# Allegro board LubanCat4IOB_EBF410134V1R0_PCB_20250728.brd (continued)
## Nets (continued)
GND: C1.2 C2.2 C3.2 C4.2 C5.2 C6.2 C7.2 C8.2 C11.2 C12.2 C13.2 C14.2 C15.2 C16.2 C17.2 C18.1 C19.2 C21.2 C22.2 C23.2 C24.2 C25.2 C26.2 C27.2 C28.2 C29.2 C30.2 C31.2 C32.2 C33.2 C34.2 C35.2 C36.2 C37.2 C38.2 C39.2 C40.2 C41.2 C42.2 C43.2 C44.2 C45.2 C46.2 C47.2 C48.2 C49.2 C50.2 C51.2 C52.2 C53.2 C54.2 C55.2 C58.2 C59.2 C60.2 C61.2 C62.2 C63.2 C64.2 C65.2 C66.2 C67.2 C68.2 C69.2 C70.2 C71.2 C72.2 C73.2 C74.2 C75.2 C76.2 C77.2 C78.2 C79.2 C80.2 C81.2 C82.2 C83.2 C84.2 C85.2 C86.2 C87.2 C88.2 C89.2 C90.2 C92.2 C93.2 C95.2 C96.2 C99.2 C100.2 C101.2 C102.1 C103.2 C104.2 C105.2 C106.2 C107.2 C108.2 C109.2 C110.2 C111.2 C112.2 C124.2 C125.2 C126.2 C127.2 C128.2 C129.2 C130.2 C131.2 C132.2 C133.2 C134.2 C135.2 C136.2 C137.2 C138.2 C139.2 C140.2 C141.2 C142.2 C143.2 C144.2 C147.2 C148.2 C149.2 C150.2 C151.2 C152.2 C153.2 C154.2 C155.2 C158.2 C159.2 C160.2 C161.2 C162.2 C163.2 C164.2 C165.2 C166.2 C167.2 C168.2 C169.2 C170.2 C171.2 C172.2 C173.2 C174.2 C175.2 C180.2 C181.2 C182.2 C183.2 C186.2 C187.2 C188.2 C189.2 C190.2 C192.2 C195.2 C196.2 C203.2 C204.2 C205.2 C206.2 C207.2 C209.2 C210.2 C211.2 C212.2 CN1.2 CN1.3 D1.1 D2.2(A) D6.1 D7.1 D8.1 D9.1 D10.1 D11.1 D12.1 D13.1 D14.1 D15.1 D16.1 D17.1 D18.1 D20.1 D21.1 D22.1 D24.1 D25.1 D26.1 D27.1 D29.1 D30.1 D31.1 D32.1 D33.1 D34.1 D35.2 D36.2 J1.1 J1.2 J1.3 J1.5 J2.2 J3.7 J3.8 J3.9 J3.10 J3.11 J3.12 J3.23 J3.29 J3.32 J3.38 J3.48 J3.51 J3.54 J3.64 J3.65 J3.68 J3.81 J3.82 J3.99 J3.100 J3.101(SH1) J3.102(SH2) J3.103(SH3) J3.104(SH4) J4.1 J4.2 J4.10 J4.11 J4.17 J4.18 J4.26 J4.27 J4.32 J4.37 J4.38 J4.43 J4.53 J4.54 J4.62 J4.72 J4.75 J4.82 J4.88 J4.94 J4.97 J4.99 J4.100 J5.1 J5.2 J5.11 J5.12 J5.17 J5.18 J5.27 J5.28 J5.33 J5.34 J5.44 J5.51 J5.52 J5.57 J5.58 J5.73 J5.76 J5.79 J5.82 J5.91 J5.100 J5.101(SH1) J5.102(SH2) J5.103(SH3) J5.104(SH4) J6.1 J6.2 J6.8 J6.14 J6.19 J6.20 J6.25 J6.30 J6.40 J6.43 J6.49 J6.67 J6.68 J6.78 J6.83 J6.84 J6.90 J6.96 J6.97 J6.98 J6.99 J6.100 J7.4 J8.2 J9.2 J9.5 J10.6(VSS) J10.10(GND10) J10.11(GND11) J10.12(GND12) J10.13(GND13) J15.10(CHS) J16.4(GND1) J16.7(GND2) J16.13(GND1) J16.16(NC3) J16.19(SH1) J16.20(SH2) J16.21(SH1) J16.22(SH2) J17.4(GND) J17.5(SH1) J17.6(SH2) J17.7(SH3) J17.8(SH4) J18.2(D2GND) J18.5(D1GND) J18.8(D0GND) J18.11(CKGND) J18.17(DDCGND) J19.6 J19.7 J19.8 J19.16 J19.19 J19.22 J19.25 J19.28 J19.31(SH1) J19.32(SH2) J20.6 J20.7 J20.8 J20.16 J20.19 J20.22 J20.25 J20.28 J20.31(SH1) J20.32(SH2) J21.4 J21.18 J21.21 J21.23 J21.24 J21.25(SH1) J21.26(SH2) J22.4 J22.18 J22.21 J22.23 J22.24 J22.25(SH1) J22.26(SH2) J23.4 J23.18 J23.21 J23.23 J23.24 J23.25(SH1) J23.26(SH2) J24.4 J24.18 J24.21 J24.23 J24.24 J24.25(SH1) J24.26(SH2) J25.4(GND9) J25.9(GND1) J25.15(GND2) J25.18(GND10) J25.21(GND3) J25.26(GND11) J25.27(GND4) J25.29(GND5) J25.34(GND12) J25.35(GND6) J25.37(GND7) J25.40(GND13) J25.43(GND8) J25.50(GND14) J25.53 J25.54 J30.A1(GND1) J30.A12(GND2) J30.B1(GND3) J30.B12(GND4) J31.5(GND) J31.8(SH1) J31.9(SH2) J31.10(SH3) J31.11(SH4) L5.2 L7.2 Q2.2(EMITTER) Q3.2(EMITTER) Q4.2(EMITTER) Q5.2(EMITTER) Q10.2(SOURCE) Q11.2(SOURCE) Q12.2(SOURCE) Q13.2(SOURCE) Q14.2(SOURCE) Q15.2(SOURCE) R4.2 R5.2 R7.2 R9.2 R16.2 R17.1 R20.2 R22.1 R24.2 R40.2 R41.2 R42.2 R64.2 R65.2 R72.2 R73.2 R83.2 R86.2 R91.2 R92.2 R98.2 R99.2 R100.2 R101.2 R102.2 R103.2 R121.2 R125.2 R142.2 R146.2 R157.2 R158.2 R159.2 R160.2 R166.2 R168.2 R174.2 R176.2 R202.2 R211.1 R214.2 R215.1 R217.2 R218.2 R219.2 R228.2 R229.2 R234.1 R235.2 R237.2 SS1.1(NC_1) SS2.1(NC_1) SS3.1(NC_1) SS4.1(NC_1) SS5.1(NC_1) SS6.1(NC_1) SW1.1(A1) SW1.2(A2) SW2.1(A1) SW2.2(A2) SW3.1(A1) SW3.2(A2) SW4.1(A1) SW4.2(A2) SW5.1(A1) SW5.2(A2) SW6.1(A1) SW6.2(A2) U1.2(GND) U2.2(GND) U3.1(GND) U4.2(PGND) U4.10(AGND) U5.1(\\O\E) U5.3(GND) U6.1(\\O\E) U6.3(GND) U7.1(GND1) U7.4(GND2) U8.4(VSS) U9.15(GND) U10.5(GND) U11.5(GND) U12.2(GND) U12.8(S) U13.2(GND) U13.8(S) U14.41(GND) U15.1(GND#1) U15.5(GND#5) U16.3(GND1) U16.8(GND2) U17.3(GND1) U17.8(GND2) U18.3(GND1) U18.8(GND2) U19.25(VSS) U20.2(GND) U21.2(GND) U22.3(GND1) U22.8(GND2) U23.3(GND1) U23.8(GND2) U24.2(GND) U25.2(GND) U26.2(GND) U27.2(GND) U28.2(GND) U29.2(GND) U30.1(GND) U32.2 U33.4(DGND) U33.13(HPGND) U33.18(AGND) U33.29(EPAD) U34.7(GND) U35.3(GND1) U35.8(GND2) U36.3(GND1) U36.8(GND2) U37.3(GND1) U37.8(GND2) U38.2(GND) U39.8(GND1) U39.9(GND2) U39.15(EPAD) Y2.2(GND1) Y2.4(GND2) Y3.2(GND1) Y3.4(GND2) Z1.1 Z2.1 Z3.2 Z4.2 Z5.1 Z6.1 Z7.1 Z8.1 Z9.1 Z10.1 Z11.1 Z12.1
VBUS_TYPEC: C196.1 C206.1 C207.1 J30.A4(VBUS1) J30.A9(VBUS2) J30.B4(VBUS3) J30.B9(VBUS4) U38.1(OUT) U39.2(VBUS)
VCC3V3_SYS: C10.1 C15.1 C16.1 C17.1 C132.1 C137.1 L1.2 R2.1 R6.1 U26.5(IN) U27.5(IN)
VCC5V0_SYS: C25.1 C26.1 C27.1 C28.1 C29.1 C31.1 C32.1 C107.1 C108.1 C131.1 C136.1 C189.1 C190.1 C203.1 C204.1 C205.1 J3.1 J3.2 J3.3 J3.4 J3.5 J3.6 L2.2 R11.1 R18.1 R34.1 R35.1 R36.1 R238.1 U2.5(IN) U4.5(VOUT) U20.5(IN) U21.5(IN) U24.5(IN) U25.5(IN) U28.5(IN) U29.5(IN) U34.6(VCC) U38.5(IN) U39.12(VCONN1) U39.13(VCONN2)
VCC_1V8_S0: J3.21 J3.22 R185.1 R188.1
VCC_1V8_S3: C35.1 J3.19 J3.20 R46.1 R47.1 R61.1
VCC_3V3_S3: C11.1 C36.1 C37.1 C40.1 C42.1 C211.1 D5.2 J3.13 J3.14 R1.1 R25.1 R29.1 R56.1 R230.1 R231.1 R232.1 R233.1 U5.5(VCC) U6.5(VCC) U39.3(VDD1) U39.4(VDD2)
VCC_3V3_SD: C58.1 C59.1 J10.4(VDD) R56.2
VCC_12V: C1.1 C2.1 C3.1 C12.1 C13.1 C14.1 C19.1 C21.1 C22.1 C23.1 C147.1 C148.1 C149.1 D1.2 F1.2 R8.1 R10.1 R15.1 U3.3(VIN) U4.1(VIN) U30.3(VIN)
VCCA1V8_CODEC: C164.1 C165.1 C174.1 C175.1 C187.1 R184.2 R200.1 R207.1 U33.2(DVDD) U33.3(PVDD)
VCCA3V3_CODEC: C172.1 C173.1 R186.1 R187.1 R189.2 R192.2 R205.1
VCCA_1V8_S0: C34.1 C162.1 C163.1 J3.17 J3.18 R23.1 R30.2 R32.2 R184.1
VCCA_3V3_S0: C33.1 C170.1 C171.1 J3.15 J3.16 R189.1
VDD_3V3: C5.1 C6.1 C54.1 C60.1 C61.1 C62.1 C63.1 C66.1 C67.1 C90.1 C94.1 C109.1 D19.2 D23.2 Q6.2(SOURCE) Q7.1(GATE) R43.1 R44.1 R110.1 R126.1 R127.1 R129.1 R130.1 R132.1 R133.1 R135.1 R148.1 R150.1 R152.1 R154.1 R161.1 R162.1 R163.1 R164.1 R240.2 U1.1(OUT) U9.16(VCC) U10.8(VCC) U11.8(VCC) U12.5(VIO) U13.5(VIO)
VDD_5V: C7.1 C8.1 C64.1 C65.1 C68.1 C69.1 D28.2 Q9.1(GATE) U2.1(OUT) U12.3(VCC) U13.3(VCC)
5V0_CAM0/1: C140.1 C141.1 J21.1 J21.2 J21.3 J22.1 J22.2 J22.3 U28.1(OUT)
5V0_CAM2/3: C143.1 C144.1 J23.1 J23.2 J23.3 J24.1 J24.2 J24.3 U29.1(OUT)
B_DM1: J16.2(D-) R116.1 U16.4(D2+) U16.7(NC3)
B_DM2: J16.11(D-) R112.1 U16.1(D1+) U16.10(NC1)
B_DM3: J17.2(D-) R114.1 U18.2(D1-) U18.9(NC2)
B_DP1: J16.3(D+) R117.1 U16.5(D2-) U16.6(NC4)
B_DP2: J16.12(D+) R113.1 U16.2(D1-) U16.9(NC2)
B_DP3: J17.3(D+) R115.1 U18.1(D1+) U18.10(NC1)
BAT_RTC: C50.1 D5.1 D6.2 J8.1
BD_CH3: C38.1 J4.48 R23.2 R24.1
CAM0/1_PWR_EN: J5.69 R165.1
CAM0_NRST: J4.6 J21.22
CAM0_PWDN: J4.4 J21.15
CAM1_NRST: J4.12 J22.22
CAM1_PWDN: J4.8 J22.15
CAM2/3_PWR_EN: J5.71 R167.1
CAM2_NRST: J4.16 J23.22
CAM2_PWDN: J4.14 J23.15
CAM3_NRST: J4.22 J24.22
CAM3_PWDN: J4.20 J24.15
CAN1_H: D24.2 R74.1 R78.1 U12.7(CANH)
CAN1_L: D25.2 R75.1 R78.2 U12.6(CANL)
CAN1_RX_M1: J4.30 U12.4(RXD)
CAN1_TX_M1: J4.28 U12.1(TXD)
CAN2_H: D26.2 R76.1 R79.1 U13.7(CANH)
CAN2_L: D27.2 R77.1 R79.2 U13.6(CANL)
CAN2_RX_M0: J4.36 U13.4(RXD)
CAN2_TX_M0: J4.34 U13.1(TXD)
CTP0_INT: J6.44 J19.11 R147.2
CTP0_RST: J5.62 J19.12 R151.2
CTP1_INT: J6.46 J20.11 R149.2
CTP1_RST: J6.70 J20.12 R153.2
DBG_RX: R27.2 U6.2(A)
DBG_RXD: J7.3 R27.1 Z4.1
DBG_TX: R26.2 U5.4(Y)
DBG_TXD: J7.2 R26.1 Z3.1
DEBUG_RX: J5.78 R29.2 U6.4(Y)
DEBUG_TX: J5.80 R25.2 U5.2(A)
EARPHONE_CTL: J5.72 R216.1
EXT_PWR_EN: J3.30 R3.1 R37.1
FAN: C24.1 Q1.2(SOURCE) R10.2 R11.2 R12.1
FAN_PWM: J5.63 R13.1
FUSB302_INT: J5.68 R232.2 U39.5(I\N\T\)
GMAC1_INT: J6.48 R96.1
GMAC1_MCLK_INOUT: J3.67 R97.1 R98.1
GMAC1_MDC: J3.95 R93.2 U14.13(MDC)
GMAC1_MDIO: J3.97 R94.2 U14.14(MDIO)
GMAC1_RSTN: C78.1 J6.50 R105.2 U14.12(PHYRSTB)
GMAC1_RXCLK: J3.85 R83.1 R89.1
GMAC1_RXD0: J3.87 R80.2 R84.1
GMAC1_RXD1: J3.89 R81.2 R85.1
GMAC1_RXD2: J3.91 R87.1 R91.1
GMAC1_RXD3: J3.93 R82.2 R88.1
GMAC1_RXDV_CRS: J3.83 R90.1 R92.1
GMAC1_TXCLK: J3.69 U14.20(TXC)
GMAC1_TXD0: J3.73 U14.18(TXD0)
GMAC1_TXD1: J3.75 U14.17(TXD1)
GMAC1_TXD2: J3.77 U14.16(TXD2)
GMAC1_TXD3: J3.79 U14.15(TXD3)
GMAC1_TXEN: J3.71 U14.19(TXCTL)
HDMI0_TX_ON: J6.89 R145.1
HDMI_5V: C124.1 D28.1 D34.2 J18.18(+5V) R128.1 R131.1
HDMI_EARC+: C121.2 D32.2 J18.14(UTILITY)
HDMI_EARC-: C122.2 D29.2 J18.19(HPD) R139.2
HDMI_TX0_CEC_M0: J4.60 Q9.2(SOURCE) R132.2
HDMI_TX0_D0N: C118.1 J6.37
HDMI_TX0_D0P: C117.1 J6.35
HDMI_TX0_D1N: C115.1 J6.33
HDMI_TX0_D1P: C114.1 J6.31
HDMI_TX0_D2N: C116.1 J6.29
HDMI_TX0_D2P: C113.1 J6.27
HDMI_TX0_D3N: C120.1 J6.41
HDMI_TX0_D3P: C119.1 J6.39
HDMI_TX0_HPD_M0: J6.92 Q10.3(DRAIN) R133.2
HDMI_TX0_SBDN: C122.1 J6.47
HDMI_TX0_SBDP: C121.1 J6.45
HDMI_TX0_SCL_M0: J4.56 Q7.2(SOURCE) R127.2
HDMI_TX0_SDA_M0: C123.2 J4.58 Q8.2(SOURCE) R129.2
HP_PLUG_IN_DET: C186.1 J5.46 R206.1
HUB_3V3: C110.1 C111.1 C112.1 R122.1 R123.1 R126.2 U19.1(OVCUR#) U19.20(VDD3V3)
HUB_DM1: R116.2 U19.11(DM1)
HUB_DM2: R112.2 U19.9(DM2)
HUB_DM3: R114.2 U19.7(DM3)
HUB_DM4: R182.2 U18.5(D2-) U18.6(NC4) U19.5(DM4)
HUB_DP1: R117.2 U19.12(DP1)
HUB_DP2: R113.2 U19.10(DP2)
HUB_DP3: R115.2 U19.8(DP3)
HUB_DP4: R183.2 U18.4(D2+) U18.7(NC3) U19.6(DP4)
I2C0_SCL_M2: J5.84 U8.6(SCL)
I2C0_SDA_M2: J5.86 U8.5(SDA)
I2C1_SCL_M2: J5.88 J23.6 R163.2 R230.2 U39.6(SCL)
I2C1_SDA_M2: J5.90 J23.5 R161.2 R231.2 U39.7(SDA)
I2C2_SCL_M4: J5.54 J19.9 J21.6 R148.2
I2C2_SDA_M4: J5.56 J19.10 J21.5 R152.2
I2C5_SCL_M3: J5.92 J20.9 J22.6 R150.2
I2C5_SDA_M3: J5.94 J20.10 J22.5 R154.2
I2C7_SCL_M0_CODEC: J5.77 R185.2 R197.1
I2C7_SDA_M0_CODEC: J5.75 R188.2 R198.1
I2C8_SCL_M2: J5.96 J24.6 R164.2
I2C8_SDA_M2: J5.98 J24.5 R162.2
I2C_ADDR_SET: R200.2 U33.26(CE)
I2S0_LRCK: J5.85 R194.1
I2S0_MCLK: J5.81 R190.1
I2S0_SCLK: J5.83 R191.1
I2S0_SDI0: J5.89 R195.1
I2S0_SDO0: J5.87 R193.1
LCD0_BL_PWM: J6.85 J19.13
LCD0_PWR_EN: J5.59 R156.1
LCD0_RST: J5.66 J19.15
LCD1_BL_PWM: J6.87 J20.13
LCD1_PWR_EN: J5.61 R155.1
LCD1_RST: J6.60 J20.15
MDIN0_PHY: J15.3(TD1-) U14.2(MDIN0)
MDIN1_PHY: J15.7(RD1-) U14.5(MDIN1)
MDIN2_PHY: J15.6(TD2-) U14.7(MDIN2)
MDIN3_PHY: J15.9(RD2-) U14.10(MDIN3)
MDIP0_PHY: J15.2(TD1+) U14.1(MDIP0)
MDIP1_PHY: J15.4(RD1+) U14.4(MDIP1)
MDIP2_PHY: J15.5(TD2+) U14.6(MDIP2)
MDIP3_PHY: J15.8(RD2+) U14.9(MDIP3)
MIC1_L: C176.2 C194.1 J27.2 J27.4 J29.1 R208.2 Z8.2
MIC1_R: C177.2 C194.2 J27.3 J27.5 J29.2 R218.1 Z11.2
MIC2_L: C178.2 R199.2
MIC2_R: C179.2 R201.2
MINIPCIE_3V3: C146.1 C150.1 C151.1 C152.1 C158.1 C159.1 C160.1 C161.1 J25.2(VBAT1) J25.24(VBAT5) J25.39(VBAT2) J25.41(VBAT3) J25.52(VBAT4) L6.2 R172.1 R177.1
MINIPCIE_NWDISABLE: J6.42 R180.2
MINIPCIE_PWR_EN: J5.74 R175.1
MIPI_CSI0_RX_CLK0N: J3.52 J23.10
MIPI_CSI0_RX_CLK0P: J3.50 J23.9
MIPI_CSI0_RX_CLK1N: J3.36 J24.10
MIPI_CSI0_RX_CLK1P: J3.34 J24.9
MIPI_CSI0_RX_D0N: J3.62 J23.12
MIPI_CSI0_RX_D0P: J3.60 J23.11
MIPI_CSI0_RX_D1N: J3.58 J23.8
MIPI_CSI0_RX_D1P: J3.56 J23.7
MIPI_CSI0_RX_D2N: J3.46 J24.12
MIPI_CSI0_RX_D2P: J3.44 J24.11
MIPI_CSI0_RX_D3N: J3.42 J24.8
MIPI_CSI0_RX_D3P: J3.40 J24.7
MIPI_DPHY0_RX_CLKN: J4.15 J21.10
MIPI_DPHY0_RX_CLKP: J4.13 J21.9
MIPI_DPHY0_RX_D0N: J4.25 J21.12
MIPI_DPHY0_RX_D0P: J4.23 J21.11
MIPI_DPHY0_RX_D1N: J4.21 J21.8
MIPI_DPHY0_RX_D1P: J4.19 J21.7
MIPI_DPHY0_RX_D2N: J4.9 J21.17
MIPI_DPHY0_RX_D2P: J4.7 J21.16
MIPI_DPHY0_RX_D3N: J4.5 J21.20
MIPI_DPHY0_RX_D3P: J4.3 J21.19
MIPI_DPHY0_TX_CLKN: J4.41 J19.24
MIPI_DPHY0_TX_CLKP: J4.39 J19.23
MIPI_DPHY0_TX_D0N: J4.51 J19.27
MIPI_DPHY0_TX_D0P: J4.49 J19.26
MIPI_DPHY0_TX_D1N: J4.47 J19.21
MIPI_DPHY0_TX_D1P: J4.45 J19.20
MIPI_DPHY0_TX_D2N: J4.35 J19.18
MIPI_DPHY0_TX_D2P: J4.33 J19.17
MIPI_DPHY0_TX_D3N: J4.31 J19.30
MIPI_DPHY0_TX_D3P: J4.29 J19.29
MIPI_DPHY1_RX_CLKN: J4.87 J22.10
MIPI_DPHY1_RX_CLKP: J4.85 J22.9
MIPI_DPHY1_RX_D0N: J4.95 J22.12
MIPI_DPHY1_RX_D0P: J4.93 J22.11
MIPI_DPHY1_RX_D1N: J4.91 J22.8
MIPI_DPHY1_RX_D1P: J4.89 J22.7
MIPI_DPHY1_RX_D2N: J4.83 J22.17
MIPI_DPHY1_RX_D2P: J4.81 J22.16
MIPI_DPHY1_RX_D3N: J4.79 J22.20
MIPI_DPHY1_RX_D3P: J4.77 J22.19
MIPI_DPHY1_TX_CLKN: J4.65 J20.24
MIPI_DPHY1_TX_CLKP: J4.63 J20.23
MIPI_DPHY1_TX_D0N: J4.73 J20.27
MIPI_DPHY1_TX_D0P: J4.71 J20.26
MIPI_DPHY1_TX_D1N: J4.69 J20.21
MIPI_DPHY1_TX_D1P: J4.67 J20.20
MIPI_DPHY1_TX_D2N: J4.61 J20.18
MIPI_DPHY1_TX_D2P: J4.59 J20.17
MIPI_DPHY1_TX_D3N: J4.57 J20.30
MIPI_DPHY1_TX_D3P: J4.55 J20.29
OTG_DM: D36.1 J30.A7(DN1) J30.B7(DN2) R221.1
OTG_DP: D35.1 J30.A6(DP1) J30.B6(DP2) R220.1
OUT1_L: C191.1 U33.12(LOUT1)
OUT1_R: C193.1 U33.11(ROUT1)
OUT2_L: R203.1 U33.15(LOUT2)
OUT2_R: R204.1 U33.14(ROUT2)
PCIE20_0_CLKN: J5.16 J25.11(VDD-EXT)
PCIE20_0_CLKP: J5.14 J25.13(RESERVED)
PCIE20_0_RXN: J5.6 J25.23(UART-RXD)
PCIE20_0_RXP: J5.4 J25.25(UART-RTS)
PCIE20_0_TXN: C156.1 J5.10
PCIE20_0_TXP: C157.1 J5.8
PCIE20X1_2_CLKREQN_M0: J6.54 R179.1
PCIE20X1_2_PERSTN_M0: J6.74 R181.2
PCIE20X1_2_WAKEN_M0: J6.56 R178.1
PE_TXN: C156.2 J25.31(UART-TXD)
PE_TXP: C157.2 J25.33(PERST2)
PHY1_CLKOUT125: R97.2 U14.35(CLKOUT)
PHY1_LED1: J15.14(YELA) R103.1 U14.33(LED1)
PHY1_LED2: J15.11(GRLA) R102.1 U14.34(LED2)
PWM7_IR_M0: C46.1 J5.70 R45.1
PWRON_EN: J3.24 R238.2
PWRON_KEY: C39.1 J3.28 SW1.3(B1) SW1.4(B2) Z1.2
RESET_KEY: C41.1 J3.26 SW2.3(B1) SW2.4(B2) Z2.2
RS485_1_A: D20.2 J11.1 R62.2 R67.1 U10.6(A)
RS485_1_B: D18.2 R63.1 R64.1 R66.1 U10.7(B)
RS485_2_A: D22.2 J13.1 R69.1 R70.2 U11.6(A)
RS485_2_B: D21.2 R68.1 R71.1 R72.1 U11.7(B)
RTC_32K_IN: J5.50 R48.2
RTC_INT: J5.48 R46.2 U8.3(\\I\N\T)
RXD1_232: D8.2 R51.1 U9.13(R1IN)
RXD2_232: D7.2 R49.1 U9.8(R2IN)
SARADC_BOOT: J4.52 R239.2
SARADC_IN1/REC: J4.50 R28.2
SARADC_IN4: J4.46 R31.2
SARADC_IN5: J4.44 R33.2
SBU_1: C201.1 J30.A8(SUB1) R226.1 R229.1 U37.1(D1+) U37.10(NC1)
SBU_2: C202.1 J30.B8(SUB2) R227.1 R228.1 U37.2(D1-) U37.9(NC2)
SDMMC_CLK: J6.77 R57.1
SDMMC_CMD: J6.79 R55.1
SDMMC_D0: J6.69 R58.1
SDMMC_D1: J6.71 R59.1
SDMMC_D2: J6.73 R53.1
SDMMC_D3: J6.75 R54.1
SDMMC_DET: J6.81 R60.1 R61.2
SIM_CLK0: J25.12(USIM-CLK) R171.1
SIM_DATA0: J25.10(USIM-DATA) R173.1
SIM_RST0: J25.14(USIM-RST) R170.1
SIM_VDD: J25.8(USIM-VDD) J31.1(VCC) R169.1 U32.1
SPK_CTRL: J4.24 R214.1 U34.1(SDN)
SS_TXN: C97.1 J16.8(TX-) U17.4(D2+) U17.7(NC3)
SS_TXP: C98.1 J16.9(TX+) U17.5(D2-) U17.6(NC4)
SSRX_1N: J30.B10(SSRXN1) R223.1 U35.5(D2-) U35.6(NC4)
SSRX_1P: J30.B11(SSRXP1) R222.1 U35.4(D2+) U35.7(NC3)
SSRX_2N: J30.A10(SSRXN2) R225.1 U36.5(D2-) U36.6(NC4)
SSRX_2P: J30.A11(SSRXP2) R224.1 U36.4(D2+) U36.7(NC3)
SSTX_1N: C198.1 J30.A3(SSTXN1) U35.1(D1+) U35.10(NC1)
SSTX_1P: C197.1 J30.A2(SSTXP1) U35.2(D1-) U35.9(NC2)
SSTX_2N: C200.1 J30.B3(SSTXN2) U36.1(D1+) U36.10(NC1)
SSTX_2P: C199.1 J30.B2(SSTXP2) U36.2(D1-) U36.9(NC2)
SYS_LED: J5.65 R38.1
TX_CEC_PORT: D33.2 J18.13(CEC) Q9.3(DRAIN)
TX_D0N_PORT: C118.2 J18.9(D0-) R136.1 U23.4(D2+) U23.7(NC3)
TX_D0P_PORT: C117.2 J18.7(D0+) R134.1 U23.5(D2-) U23.6(NC4)
TX_D1N_PORT: C115.2 J18.6(D1-) R138.1 U22.1(D1+) U22.10(NC1)
TX_D1P_PORT: C114.2 J18.4(D1+) R137.1 U22.2(D1-) U22.9(NC2)
TX_D2N_PORT: C116.2 J18.3(D2-) R141.1 U22.4(D2+) U22.7(NC3)
TX_D2P_PORT: C113.2 J18.1(D2+) R140.1 U22.5(D2-) U22.6(NC4)
TX_D3N_PORT: C120.2 J18.12(CK-) R144.1 U23.1(D1+) U23.10(NC1)
TX_D3P_PORT: C119.2 J18.10(CK+) R143.1 U23.2(D1-) U23.9(NC2)
TX_ON: Q12.1(GATE) Q13.1(GATE) Q14.1(GATE) Q15.1(GATE) R145.2 R146.1
TX_SCL_PORT: D31.2 J18.15(SCL) Q7.3(DRAIN) R128.2
TX_SDA_PORT: D30.2 J18.16(SDA) Q8.3(DRAIN) R131.2
TXD1_232: D10.2 R52.1 U9.14(T1OUT)
TXD2_232: D9.2 R50.1 U9.7(T2OUT)
TYPE_C_PWR_EN: J6.66 R236.1
TYPEC0_OTG_DM: J4.98 R221.2
TYPEC0_OTG_DP: J4.96 R220.2
TYPEC0_OTG_VBUSDET: J4.92 R233.2
TYPEC0_SBU1/DP0_AUXP: C201.2 J4.84
TYPEC0_SBU1_DC: J6.93 R226.2
TYPEC0_SBU2/DP0_AUXN: C202.2 J4.86
TYPEC0_SBU2_DC: J6.95 R227.2
TYPEC0_SSRX1N/DP0_TX0N: J4.80 R223.2
TYPEC0_SSRX1P/DP0_TX0P: J4.78 R222.2
TYPEC0_SSRX2N/DP0_TX2N: J4.70 R225.2
TYPEC0_SSRX2P/DP0_TX2P: J4.68 R224.2
TYPEC0_SSTX1N/DP0_TX1N: C198.2 J4.76
TYPEC0_SSTX1P/DP0_TX1P: C197.2 J4.74
TYPEC0_SSTX2N/DP0_TX3N: C200.2 J4.66
TYPEC0_SSTX2P/DP0_TX3P: C199.2 J4.64
TYPEC0_USB20_OTG_ID: J4.90 R234.2
TYPEC_CC1: C210.1 J30.A5(CC1) U37.4(D2+) U37.7(NC3) U39.10(CC1_1) U39.11(CC1_2)
TYPEC_CC2: C209.1 J30.B5(CC2) U37.5(D2-) U37.6(NC4) U39.1(CC2_1) U39.14(CC2_2)
UART0_RX_M0: J5.60 U9.9(R2OUT)
UART0_TX_M0: J5.64 U9.10(T2IN)
UART4_DIR: J6.72 R65.1 U10.2(R\E\) U10.3(DE)
UART4_RX_M2: J5.97 U10.1(RXD)
UART4_TX_M2: J5.99 U10.4(TXD)
UART7_DIR: J6.94 R73.1 U11.2(R\E\) U11.3(DE)
UART7_RX_M2: J5.93 U11.1(RXD)
UART7_TX_M2: J5.95 U11.4(TXD)
UART9_RX_M2: J6.76 U9.12(R1OUT)
UART9_TX_M2: J6.58 U9.11(T1IN)
USB20_HOST0_DM: J6.88 R120.2
USB20_HOST0_DP: J6.86 R119.2
USB20_HOST1_DM: J6.82 R109.1
USB20_HOST1_DP: J6.80 R108.1
USB20_PWR_EN: J6.64 R124.1
USB20_VBUS: C105.1 C106.1 J16.10(VBUS) J17.1(VCC) U21.1(OUT)
USB30_PWR_EN: J6.62 R118.1
USB30_SSRXN: J5.21 J16.5(RX-) U17.1(D1+) U17.10(NC1)
USB30_SSRXP: J5.19 J16.6(RX+) U17.2(D1-) U17.9(NC2)
USB30_SSTXN: C97.2 J5.25
USB30_SSTXP: C98.2 J5.23
USB30_VBUS: C99.1 C101.1 J16.1(VBUS) U20.1(OUT)
USER_LED: J5.67 R39.1
WLAN_PWR_EN: J6.52 R111.1
N02088: F1.1 J1.4
N03633: C9.1 U3.6(BOOT)
N03641: C9.2 L1.1 U3.2(SW)
N03801: C10.2 R6.2 R7.1 U3.4(FB)
N15118646: R1.2 R2.2 U1.5(IN)
N15118698: C4.1 R3.2 U1.4(EN) U2.4(EN)
N15119063: R4.1 U1.3(ISET)
N15123057: R5.1 U2.3(ISET)
N15599533: R84.2 U14.25(RXD0)
N15599537: R85.2 U14.24(RXD1)
N15599541: R87.2 U14.23(RXD2)
N15599545: R88.2 U14.22(RXD3)
N15599549: R89.2 U14.27(RXC)
N15599553: R90.2 U14.26(RXCTL)
N15600826: R95.2 R96.2 U14.31(INTB)
N15601838: C74.1 U14.37(XTAL_OUT) Y2.1
N15601846: C75.1 U14.36(XTAL_IN) Y2.3
N15602572: R104.1 U14.32(LED0)
N15603170: C76.1 J15.1(CT)
N15603215: C77.1 J15.15(SH) J15.16(SH1) R101.1
N15604636: J15.12(GRLC) R100.1
N15605512: R86.1 U14.39(RSET)
N15611443: C100.1 R118.2 U20.4(EN)
N15611553: R121.1 U20.3(ISET)
N15654067: R125.1 U21.3(ISET)
N15659726: C18.2 R8.2 R9.1 U3.5(EN)
N15752445: J18.G1(GND1) J18.G2(GND2) J18.G3(GND3) J18.G4(GND4) L5.1
N16793147: D11.2 J10.1(DAT2) R53.2
N16793149: D15.2 J10.7(DAT0) R58.2
N16793151: D14.2 J10.5(CLK) R57.2
N16793153: D13.2 J10.3(CMD) R55.2
N16793155: D12.2 J10.2(CD/DAT3) R54.2
N16793157: D16.2 J10.8(DAT1) R59.2
N16793300: D17.2 J10.9(CD) R60.2
N16811933: J25.1(MIC-P) R177.2 R178.2
N16823854: J25.7(SPK-N) R179.2
N16928945: J25.20(W-DISABLE) R180.1
N16929135: J25.22(PERST1) R181.1
N16980859: C155.1 J31.2(RST) R170.2 U32.6
N16980861: C154.1 J31.3(CLK) R171.2 U32.4
N16980863: C153.1 J31.7(I/O) R169.2 R173.2 U32.5
N17454508: C56.2 U9.1(C1+)
N17454513: C56.1 U9.3(C1-)
N17455367: C57.2 U9.4(C2+)
N17455372: C57.1 U9.5(C2-)
N17455499: C55.1 U9.6(V-)
N17455508: C53.1 U9.2(V+)
N17466585: L3.1 U14.30(REG_OUT)
N17592125: C145.1 U30.6(BOOT)
N17592129: C145.2 L6.1 U30.2(SW)
N17592172: C146.2 R172.2 R174.1 U30.4(FB)
N17592220: R175.2 R176.1 U30.5(EN)
N17633217: C103.1 U19.3(XOUT) Y3.1
N17633237: C102.2 U19.4(XIN) Y3.3
N17633305: R123.2 U19.18(PSELF)
N17633317: R122.2 U19.16(RESET#/CDP)
N17695706: C128.1 R156.2 U25.4(EN) U26.4(EN)
N17695791: R159.1 U26.3(ISET)
N17695827: R158.1 U25.3(ISET)
N17697466: J15.13(YELC) R99.1
N17697880: R166.1 U28.3(ISET)
N17697953: C139.1 R165.2 U28.4(EN)
N17702194: J12.3 R68.2
N17702199: J12.4 R69.2
N17702222: J12.2 R67.2
N17702231: J12.1 R66.2
N17728858: D19.1 R62.1
N17729021: D23.1 R70.1
N17731608: J9.4 R51.2
N17731627: J9.1 R49.2
N17750545: Q1.1(GATE) Q2.3(COLLECTOR) R12.2
N17750554: D2.1(K) J2.1 Q1.3(DRAIN)
N17750632: Q2.1(BASE) R13.2 R16.1
N17770939: R119.1 U19.15(DPU)
N17770942: R120.1 U19.14(DMU)
N17946485: C43.1 R28.1 SW3.3(B1) SW3.4(B2) Z5.2
N18056005: C94.2 Q6.1(GATE) R110.2 R111.2
N18056634: C91.1 C92.1 U15.2(RF0)
N18056637: C91.2 C93.1 CN1.1
N18057251: J25.36(USB-D-) R182.1
N18057253: J25.38(USB-D+) R183.1
N18057325: R109.2 U15.7(D-)
N18057335: R108.2 U15.6(D+)
N18111918: C125.1 R155.2 U24.4(EN) U27.4(EN)
N18111989: R160.1 U27.3(ISET)
N18112037: R157.1 U24.3(ISET)
N18115454: R168.1 U29.3(ISET)
N18115527: C142.1 R167.2 U29.4(EN)
N18211307: C30.1 R19.1 R21.1 U4.9(VCC)
N18211553: C20.2 L2.1 U4.7(SW)
N18211596: R19.2 U4.3(PG)
N18211602: R21.2 R22.2 U4.6(MODE)
N18211651: R18.2 R20.1 U4.11(FB)
N18211688: R14.1 U4.8(BST)
N18211692: C20.1 R14.2
N18213641: R15.2 R17.2 U4.12(EN)
N18241743: J30.1(SH1) J30.2(SH2) J30.3(SH3) J30.4(SH4) L7.1
N18284542: C123.1 Q8.1(GATE) R130.2
N18285221: Q10.1(GATE) Q11.3(DRAIN) R135.2
N18285616: Q11.1(GATE) R139.1 R142.1
N18287294: Q15.3(DRAIN) R134.2 R136.2
N18287307: Q14.3(DRAIN) R137.2 R138.2
N18287331: Q13.3(DRAIN) R140.2 R141.2
N18287355: Q12.3(DRAIN) R143.2 R144.2
N18312149: R198.2 U33.27(CDATA)
N18312152: R197.2 U33.28(CCLK)
N18312155: R195.2 U33.8(ASDOUT)
N18312158: R194.2 U33.7(LRCK)
N18312161: R193.2 U33.6(DSDIN)
N18312164: R191.2 U33.5(SCLK)
N18312167: R190.2 U33.1(MCLK)
N18314752: C166.1 C167.1 R186.2 U33.17(AVDD)
N18314935: C168.1 C169.1 R187.2 U33.16(HPVDD)
N18315822: C176.1 U33.24(LIN1)
N18315825: C177.1 U33.23(RIN1)
N18315828: C178.1 U33.22(LIN2)
N18315831: C179.1 U33.21(RIN2)
N18315834: C180.1 U33.20(VMID)
N18315837: C181.1 U33.19(ADCVREF)
N18315840: C182.1 U33.10(VREF)
N18319040: C184.1 P1.1(OUT) R196.2 R199.1
N18319047: C184.2 P1.2(GND) R201.1 R202.1
N18319296: C183.1 R192.1 R196.1
N18351323: J14.3 R76.2
N18351325: J14.4 R77.2
N18351329: J14.2 R75.2
N18351335: J14.1 R74.2
N18375618: D3.1(CATHODE) Q4.3(COLLECTOR)
N18375621: D3.2(ANODE) R35.2
N18375775: Q4.1(BASE) R38.2 R41.1
N18376132: D4.1(CATHODE) Q5.3(COLLECTOR)
N18376134: D4.2(ANODE) R36.2
N18376144: Q5.1(BASE) R39.2 R42.1
N18437233: R235.1 U38.3(ISET)
N18438798: R236.2 R237.1 U38.4(EN)
N18458541: C44.1 R30.1 R31.1 SW4.3(B1) SW4.4(B2) Z6.2
N18458605: C45.1 R32.1 R33.1 SW5.3(B1) SW5.4(B2) Z7.2
N18463759: LED1.1(CATHODE) Q3.3(COLLECTOR)
N18463775: LED1.2(ANODE) R34.2
N18463803: Q3.1(BASE) R37.2 R40.1
N18464833: R43.2 R45.2 U7.3(OUT)
N18464854: C47.1 C48.1 R44.2 U7.2(VCC)
N18479746: J26.1 R217.1
N18479761: J26.3 J26.5 Q17.2(SOURCE) Z10.2
N18479774: J26.2 Q16.2(SOURCE) R206.2 Z9.2
N18480030: J26.4 R205.2
N18480910: C188.1 R207.2 R208.1
N18480944: J27.1 R219.1
N18528085: J9.6 R52.2
N18528088: J9.3 R50.2
N18639472: J28.2 R212.2 U34.5(VO1)
N18639500: R209.2 R212.1 U34.4(IN-)
N18639545: C192.1 U34.2(BYPASS) U34.3(IN+)
N18639570: C185.1 R203.2 R204.2
N18639588: C185.2 R209.1
N18642135: C52.1 U8.2(OSCO) Y1.2
N18642163: C51.1 U8.1(OSCI) Y1.1
N18642204: C49.1 D5.3 U8.8(VDD)
N18642319: R47.2 R48.1 U8.7(CLKOUT)
N18645225: Q16.3(DRAIN) R210.2 R211.2
N18645232: Q17.3(DRAIN) R213.2 R215.2
N18645288: C193.2 R213.1
N18645295: C191.2 R210.1
N18645705: C195.1 Q16.1(GATE) Q17.1(GATE) R216.2
N18647092: J28.1 U34.8(VO2)
N18656178: C104.1 R124.2 U21.4(EN)
N18804334: J11.2 R63.2
N18804414: J13.2 R71.2
N18903114: C212.1 R239.1 SW6.3(B1) SW6.4(B2) Z12.2

Pads without a net: J3 25 27 31 33 35 37 39 41 43 45 47 49 53 55 57 59 61 63 66 70 72 74 76 78 80 84 86 88 90 92 94 96 98; J4 40 42; J5 3 5 7 9 13 15 20 22 24 26 29 30 31 32 35 36 37 38 39 40 41 42 43 45 47 49 53 55; J6 3 4 5 6 7 9 10 11 12 13 15 16 17 18 21 22 23 24 26 28 32 34 36 38 51 53 55 57 59 61 63 65 91; J7 1; J16 14 15 17 18; J19 14; J20 14; J21 13 14; J22 13 14; J23 13 14 16 17 19 20; J24 13 14 16 17 19 20; J25 3 5 6 16 17 19 28 30 32 42 44 45 46 47 48 49 51; J31 4 6; U4 4; U15 3 4 9 10 11 12 13 14; U19 2 13 17 19 21 22 23 24; U32 3; U33 9 25

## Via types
v1: diameter 0.508, hole 0.254, TOP to BOTTOM, 1912 vias

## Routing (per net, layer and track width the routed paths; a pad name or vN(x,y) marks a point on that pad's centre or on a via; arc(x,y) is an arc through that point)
1V05_AVDD_PHY: length 21.7
  TOP w0.381: v1(112.52,72.64) v1(110.49,72.64) 109.7,73.43 105.66,73.43 105.38,73.15 v1(104.01,73.15)
  BOTTOM w0.203: U14.8 112.63,72.53 v1(112.52,72.64) ; 108.22,69.32 U14.38 ; v1(110.49,72.64) 110.62,72.52 110.62,72.26 110.63,72.25 U14.3
  BOTTOM w0.254: C85.1 107.31,70.24 107.31,70.23 108.22,69.32
  BOTTOM w0.305: v1(110.49,72.64) C84.1 ; C83.1 112.65,72.77 v1(112.52,72.64)
  BOTTOM w0.381: C85.1 105.65,71 105.64,70.99 R107.2 C86.1 105.02,72.14 v1(104.01,73.15)
1V05_DVDD_PHY: length 1
  BOTTOM w0.203: U14.21 113.43,64.97 v1(113.51,64.9)
1V05_PHY: length 15.2
  TOP w0.381: v1(101.85,65.53) 102.45,64.93 104.27,64.93 104.65,64.55 104.65,61.85 105.03,61.47 106.55,61.47
  BOTTOM w0.381: R107.1 102.49,70.99 101.98,70.48 101.98,65.66 v1(101.85,65.53)
  vias: v1(106.3,60.07) v1(107.44,60.07)
3V3_DVDD_PHY: length 46.6
  TOP w0.254: v1(110.49,63.88) 110.49,62.69 110.23,62.44 v1(105.55,62.44) ; v1(115.44,72.64) 116.03,73.23 120.27,73.23 120.78,72.72 v1(120.78,69.72)
  TOP w0.381: 111.25,71.63 111,71.88 110.41,71.88 109.65,72.64 v1(108.84,72.64)
  ART03 w0.254: v1(110.49,63.88) 110.61,63.76 v1(117.35,63.76)
  ART03 w0.305: v1(117.35,60.32) 116.53,59.51 115.13,59.51 v1(114.3,58.67) v1(113.16,58.67)
  BOTTOM w0.203: 114.13,70.57 U14.11
  BOTTOM w0.254: R105.1 117.73,72.4 C87.1 ; R94.1 R93.1 v1(120.78,69.72) ; 114.13,70.57 114.13,70.95 114.43,71.25 v1(114.43,72.64) ; v1(117.35,63.76) v1(117.35,60.32) 117.35,60.21 R82.1 ; R81.1 v1(114.3,58.67) ; R80.1 v1(113.16,58.67)
  BOTTOM w0.305: R95.1 v1(105.55,62.44) R104.2
  BOTTOM w0.381: C89.1 v1(114.43,72.64)
  vias: v1(110.49,64.9)
3V3_IMAGE0: length 10.4
  BOTTOM w0.254: R151.1 R147.1 121.79,77.22 121.79,80.12 121.97,80.3 121.97,81.91 122.22,82.17 125.35,82.17
  vias: v1(126.87,93.09) v1(127.76,93.09)
3V3_IMAGE1: length 7
  TOP w0.254: v1(122.56,73.79) 122.56,68.59 122.56,68.58
  BOTTOM w0.254: R149.1 R153.1 v1(122.56,73.79)
3V3_WLAN:
  vias: v1(97.41,47.5) v1(98.3,47.5)
5V0_IMAGE0:
  vias: v1(127.18,87.5) v1(127.18,86.5)
GND: length 3580.5
  TOP w0.152: 39.71,36.11 v1(40.05,36.45) ; 34.92,57.44 v1(35.01,57.52) 34.92,57.6 34.92,62.42 v1(35.01,62.5) 34.92,62.58 34.92,65.58 v1(34.99,65.64) ; v1(34.67,51.81) v1(34.67,53.59) 34.92,53.85 34.92,55.03 v1(35.02,55.12) 34.92,55.21 ; 41.81,88.67 v1(41.78,88.64) ; 78.59,57.94 78.04,58.49 76.85,58.49 75.44,57.07 v1(75.44,57.02) ; v1(57.31,19.56) 57.31,21.24 59.28,23.21 ; 42.8,68.2 42.12,68.2 40.51,66.59 40.51,66.16 ; v1(36.32,65.66) v1(36.32,62.48) v1(36.32,57.53) v1(36.32,55.12) 36.32,53.08 36.59,52.81 36.59,51.96 v1(36.45,51.81) ; v1(21.46,59.05) 21.34,59.18 21.34,62.61 v1(21.08,62.86) ; 69.35,30.36 v1(69.47,30.48) ; J3.9 v1(25.31,27.05) v1(25.31,26.25) J3.10 ; v1(34.16,70.34) 34.64,69.86 37.94,69.86 ; v1(122.45,46.1) 123.6,47.25 ; 68.7,89.09 U23.8 ; U15.5 100.55,41.43 100.08,41.91 100.08,44.19 v1(99.31,44.96) 98.81,44.45 95.12,44.45 92.96,46.61 v1(92.96,47.62) ; J16.20 78.54,87.89 78.54,83.35 C147.2 ; v1(22.86,59.05) 22.99,59.18 ; J3.12 J3.11 ; 8,65.15 8.66,65.15 8.97,65.45 8.97,69.77 8.64,70.1 v1(8,70.1) ; v1(99.31,47.5) 98.68,46.86 95.12,46.86 94.49,47.5 v1(94.49,47.62) 94.49,50.54 88.9,56.13 v1(88.9,56.39) 86.74,58.55 v1(83.19,58.55) ; 36.51,30.42 v1(36.07,30.86) ; 104.78,74.42 v1(105.54,75.18) ; J3.7 J3.8 ; v1(30.48,88.26) 30.48,88.16
  TOP w0.203: J6.14 51.68,75.68 ; J5.91 v1(67.28,26.85) 65.17,26.85 64.88,27.14 J5.79 ; J6.2 J6.1 49.28,71.03 ; J6.2 49.28,75.72 ; J6.2 48.87,75.01 ; v1(29.84,76.07) 29.71,75.94 J4.32 ; v1(59.08,26.77) 59.28,26.57 J5.52 59.28,24.47 ; v1(59.08,26.77) v1(58.08,26.77) ; v1(59.08,26.77) 59.28,26.97 J5.51 59.28,28.88 ; v1(59.08,26.77) v1(60.08,26.77) ; 36.91,24.38 J3.68 36.91,26.12 v1(37.21,26.41) ; J5.103 70.26,28 ; J5.103 v1(69.35,26.85) ; J5.103 69.35,29.03 ; v1(36.45,81.28) 36.45,81.28 ; v1(35.61,26.41) 35.71,26.41 36.11,26.01 J3.64 36.11,24.52 ; J4.88 40.91,75.8 ; v1(60.08,26.77) 60.48,27.17 J5.57 60.48,28.86 ; v1(60.08,26.77) 60.48,26.37 ; J6.99 68.88,72.42 v1(69.02,72.57) ; J6.99 68.88,70.9 ; J6.99 69.4,71.61 ; J4.94 42.11,75.76 ; J6.96 J6.98 J6.100 69.36,75.01 ; 34.11,24.42 J3.54 34.11,26.45 33.71,26.85 J3.51 33.71,28.87 ; 39.71,24.37 J3.82 39.71,26.39 v1(39.73,26.41) 39.71,26.44 J3.81 39.71,28.95 ; 22.98,71.61 J4.1 23.71,70.93 ; 51.28,28.91 J5.11 51.28,27.06 v1(50.81,26.6) 51.28,26.13 J5.12 51.28,24.3 ; 49.28,24.48 J5.2 J5.1 49.28,28.91 ; 52.88,70.81 J6.19 52.88,72.31 v1(52.96,72.39) ; 57.68,24.51 J5.44 57.68,26.37 v1(58.08,26.77) ; J5.73 63.68,30.12 v1(63.35,30.45) ; J6.78 64.48,75.77 ; 29.71,24.41 J3.32 29.71,26.18 29.31,26.58 J3.29 29.31,28.91 ; 39.71,75.6 J4.82 39.71,73.61 39.31,73.2 v1(38.68,73.2) 38.51,73.03 J4.75 38.51,70.91 ; J5.100 68.88,24.46 ; 52.48,28.87 J5.17 52.48,27.19 v1(53.08,26.6) 53.03,26.6 52.48,26.05 J5.18 52.48,24.46 ; 54.48,24.51 J5.28 54.48,26.17 v1(55.08,26.77) 54.89,26.77 54.48,27.18 J5.27 54.48,28.94 ; J4.54 34.11,74.41 33.82,74.12 33.82,73.06 v1(33.86,73.02) 34.11,72.77 J4.53 34.11,70.72 ; 30.91,24.35 J3.38 30.91,26.07 31.37,26.53 v1(31.37,26.92) ; 43.31,71 J4.99 43.64,71.61 ; 69.99,25.35 J5.104 69.35,24.32 ; J6.97 68.48,70.9 ; v1(58.08,26.77) v1(57.08,26.77) v1(56.08,26.77) ; C58.2 C59.2 ; J6.8 50.48,75.7 ; J6.83 65.68,70.96 ; 30.91,70.9 J4.37 30.91,72.44 v1(31.11,72.64) 30.91,72.85 J4.38 30.91,75.64 ; v1(56.08,26.77) 55.68,27.17 J5.33 55.68,28.99 ; v1(56.08,26.77) 55.68,26.37 J5.34 55.68,24.34 ; C183.2 v1(55.88,84.58) ; J4.18 26.91,75.98 ; J6.84 65.68,75.85 ; J5.82 65.28,24.45 ; J3.48 32.91,24.39 ; J6.43 57.68,71 ; v1(63.93,24.05) 64.08,24.2 J5.76 ; 32.11,70.85 J4.43 32.11,72.5 v1(32.26,72.64) ; 43.31,24.39 J3.100 J3.99 43.31,28.97 ; J4.17 26.91,70.84 ; J4.10 25.31,73.8 v1(25.4,73.71) ; v1(28.41,26.62) 28.11,26.91 J3.23 28.11,28.7 28.37,28.96 ; 52.88,75.65 J6.20 52.88,74.45 53.29,74.04 v1(53.55,74.04) 53.55,73.41 54.08,72.88 J6.25 54.08,71 ; v1(66.95,76.2) 66.88,76.13 J6.90 ; v1(46.23,81.28) 47.12,82.17 v1(56.26,82.17) ; J6.30 54.88,75.56 ; J6.68 62.48,75.75 ; J4.72 37.71,75.77 ; J4.27 28.91,70.55 v1(28.92,70.55) ; J4.97 42.91,70.93 ; J4.2 23.15,75.01 ; J3.65 36.51,28.82 ; J4.62 35.71,75.57 ; J4.11 25.71,70.86 ; v1(61.08,26.77) 60.88,26.77 60.48,26.37 ; J4.26 28.51,75.77 ; J5.58 60.48,26.37 ; J6.49 58.88,70.91 ; J4.100 43.31,75.75 ; J6.67 62.48,70.85 ; J6.40 56.88,75.67
  TOP w0.254: J18.11 67.5,94.98 ; SW3.1 v1(5.71,26.7) ; v1(62.61,82.42) 62.65,82.46 Q13.2 ; 78.59,57.94 78.59,56.23 73.86,51.51 67.64,51.51 62.48,46.35 59.49,46.35 53.34,40.21 v1(53.34,38.35) ; U4.10 6.74,70.61 6.76,70.64 7.46,70.64 v1(8,70.1) ; J18.2 63,95.11 ; v1(64.26,88.14) U22.8 U22.3 64.26,90.61 63.88,90.99 v1(63.88,91.06) ; C76.2 122.18,82.92 v1(121.79,83.31) ; J20.19 127.84,75.74 v1(127.89,75.69) ; v1(51.94,41.45) 52.48,41.45 58.67,47.65 62,47.65 v1(64.26,49.91) 67.02,52.67 71.09,52.67 v1(75.44,57.02) ; v1(73.93,82.19) 73.36,82.19 Q12.2 73.57,82.94 R146.2 ; D36.2 32.77,93.35 v1(31.86,94.26) ; J22.21 124.68,45.75 v1(124.59,45.85) ; 127.65,74.25 J20.16 125.43,74.25 v1(125.35,74.17) ; v1(65.79,95.12) 66,94.91 J18.8 ; v1(43.05,60.3) 43.03,60.32 40.77,60.32 40.39,59.94 40.51,59.82 v1(40.51,57.53) v1(40.51,55.12) v1(40.51,52.7) 39.62,51.81 v1(38.23,51.81) v1(36.45,51.81) v1(34.67,51.81) v1(32.89,51.81) v1(31.11,51.81) 30.86,52.07 30.86,53.34 v1(31.11,53.59) v1(31.11,55.12) 31.11,55.5 32.64,57.02 32.64,62.36 32.51,62.48 v1(32.51,62.99) ; v1(81.15,49.91) 80.62,50.44 68.61,50.44 67.28,49.11 67.28,47.14 v1(67.82,46.61) v1(67.82,45.59) 66.96,44.74 59.8,44.74 55.37,40.31 v1(55.37,38.35) ; 64.24,94.97 64.5,94.71 J18.5 ; v1(62.74,54.1) 62.74,54.25 65.32,56.83 69.08,56.83 v1(73.43,61.19) 74.85,62.61 91.9,62.61 v1(92.33,62.18) ; 127.73,44.25 J22.24 125.31,44.25 ; 127.41,69.74 J20.7 125.56,69.74 ; SW3.2 v1(3.49,26.7) ; v1(65.79,82.42) 65.82,82.46 Q14.2 ; J20.28 127.87,80.25 v1(127.89,80.26) ; J18.17 70.5,94.98 ; J22.18 125.46,47.25 ; J20.25 127.88,78.74 v1(127.89,78.74) ; 125.55,69.25 J20.6 127.38,69.25 ; R174.2 v1(82.68,78.45) 85.38,78.45 87.13,80.2 93.66,80.2 v1(94.11,80.64) ; 125.55,70.25 J20.8 127.41,70.25 ; v1(127.89,77.21) 127.86,77.25 J20.22 ; v1(18.54,65.15) 18.54,65.81 19.43,66.7 19.43,70.43 19.94,70.94 23.19,70.94 ; J24.18 125.12,25.25 v1(125.09,25.27) ; J3.101 v1(22.56,28) ; v1(68.99,82.46) Q15.2 ; v1(127.64,23.75) J24.21 125.49,23.75 ; v1(47.5,62.48) 46.96,63.02 44.86,63.02 v1(44.32,62.48) 43.79,61.95 41.68,61.95 41,62.64 41,65.91 40.74,66.16 40.51,66.16 ; D35.2 v1(34.8,92.58) ; v1(68.94,88.14) 68.94,88.28 68.71,88.52 U23.8 U23.3 ; J22.23 127.73,44.75
  TOP w0.305: v1(99.31,80.64) 99.6,80.35 J25.43 ; J25.26 106.4,72.08 106.1,72.39 v1(105.79,72.39) ; J3.104 43.79,24.33 ; J3.104 v1(43.79,26.51) ; J3.104 44.62,25.35 v1(44.79,25.51) ; J5.101 48.8,26.53 v1(48.79,26.51) 48.8,26.5 J5.102 ; J5.101 48.07,28 ; J5.101 48.8,28.82 ; J22.4 127.69,54.25 ; v1(68.94,88.14) 68.94,86.44 v1(68.91,86.41) ; J3.103 44.5,28 ; J3.103 v1(43.79,26.51) ; J3.103 43.79,28.83 ; v1(43.79,26.51) v1(44.79,26.51) ; J5.102 48.8,24.49 ; J5.102 48.22,25.35 ; J25.9 116.4,77.92 116.2,77.72 v1(116.2,77.72) ; v1(118.4,72.64) J25.4
  TOP w0.381: v1(10.09,10.02) U7.1 10.09,12.38 v1(10.54,12.83) ; D11.1 v1(113.79,26.54) ; D12.1 v1(112.52,26.54) ; D14.1 v1(107.7,26.54) ; J22.26 130.3,56.31 130.3,55.5 ; v1(110.36,69.59) 109.6,70.35 J25.18 ; D29.1 74.92,90.54 v1(74.93,90.55) ; D32.1 71.89,88.87 v1(72.09,88.67) ; D16.1 v1(105.16,26.54) ; v1(14.61,10.03) 13.9,10.73 U7.4 ; C58.2 108.97,26.53 v1(108.97,26.54) ; v1(122.53,80.52) 122.45,80.44 J25.54 ; D17.1 v1(103.89,26.54) ; D13.1 v1(111.25,26.54) ; D15.1 v1(106.43,26.54) ; 16.06,23.75 16.06,24.29 SS2.1
  TOP w0.508: v1(40.05,36.45) 40.05,37.63 56.51,54.1 v1(57.66,54.1) v1(62.74,54.1) ; J25.15 114,77.89 ; SS4.1 76.45,70.2 71.35,70.2 66.04,64.89 53.03,64.89 47.38,59.24 v1(47.05,59.24) ; 100.8,69.55 J25.40 100.8,72.25 ; 96.8,69.29 J25.50 96.8,72.36 v1(96.77,72.39) ; v1(88.65,68.71) v1(82.04,68.71) v1(79.5,68.71) 71.9,68.71 v1(66.71,63.52) 53.74,63.52 v1(49.47,59.24) ; v1(91.19,73.79) 90.81,73.4 90.81,69.86 v1(89.65,68.71) ; 105.2,77.52 J25.29 105.2,80.55 v1(105.28,80.63) ; v1(102.8,77.72) J25.35 102.8,80.19 v1(103.25,80.63) ; v1(108.46,77.72) 108.4,77.78 J25.21 108.4,80.54 ; v1(89.98,77.78) 90.55,78.36 93.01,78.36 J25.53 ; 102,77.8 J25.37 102,80.4 ; J25.43 99.6,77.79 ; v1(95.63,64.26) 93.73,66.17 v1(91.91,66.17) v1(79.43,66.17) 73.23,66.17 67.59,60.53 63.54,60.53 60.93,57.92 55.14,57.92 36.44,39.22 36.44,38.42 36.44,31.23 v1(36.07,30.86) ; v1(88.65,67.41) 72.43,67.41 67.1,62.08 v1(66.72,62.08) 55.03,62.08 v1(55.02,62.1) ; J25.27 v1(106,77.72) ; J25.26 106.4,69.55 ; J25.34 103.2,72.34 v1(103.25,72.39)
  TOP w0.533: J24.26 130.34,35.45 ; J24.26 127.98,35.45 ; J24.26 129.16,36.43 ; 116.63,26.95 SS5.1 ; SS5.1 119.9,30.23 ; SS5.1 119.9,23.67 ; SS5.1 123.18,26.95 ; 127.98,57.45 J22.26 129.16,58.43 ; 116.83,21.5 J10.13 ; J10.13 117.9,22.57 ; J10.13 118.97,21.5 ; J10.13 117.9,20.44 ; J17.7 100.53,93.1 ; J17.7 97.97,93.1 ; J17.7 99.25,91.82 ; J17.7 99.25,94.38 ; 129.21,65.57 J20.32 129.21,63.62 ; 102.52,21.5 J10.10 ; J10.10 103.3,20.44 ; J10.10 103.3,22.57 ; J24.25 129.16,21.53 ; J24.25 127.98,20.55 ; J24.25 130.34,20.55 ; J24.25 129.16,19.57 ; SS6.1 95.7,30.23 ; SS6.1 95.7,23.67 ; SS6.1 92.43,26.95 ; SS6.1 98.98,26.95 ; J10.11 104.24,11.9 ; J10.11 103.3,10.52 ; J10.11 102.36,11.9 ; J10.11 103.3,13.29 ; 13.3,23.77 SS2.1 ; SS2.1 10.02,27.05 ; SS2.1 16.57,27.05 ; SS2.1 13.3,30.33 ; J17.6 104.75,94.38 ; J17.6 106.03,93.1 ; J17.6 103.47,93.1 ; J17.6 104.75,91.82 ; 18.77,99.52 J1.5 ; J1.5 18.1,100.9 ; J1.5 19.45,100.9 ; J20.31 130.39,83.39 ; J20.31 129.21,82.42 ; J20.31 128.03,83.39 ; J20.31 129.21,84.37 ; J16.7 87.64,91.88 ; J16.7 86.19,91.88 ; J16.7 86.92,91.15 ; J16.7 86.92,92.61 ; J2.2 24.74,87.53 ; J2.2 25.44,86.83 ; J2.2 24.74,86.13 ; J9.2 53.79,13.05 ; J9.2 52.71,11.97 ; J9.2 51.64,13.05 ; 40.21,13.05 J9.5 ; J9.5 42.36,13.05 ; J9.5 41.28,11.97 ; J16.19 82.12,95.38 ; J16.19 80.35,93.6 ; J16.19 78.57,95.38 ; J8.2 18.57,85.21 ; J8.2 17.94,84.58 ; J8.2 17.94,85.83 ; 17,93.65 J1.3 ; J1.3 17.92,95.18 ; J1.3 18.85,93.65 ; J1.3 17.92,92.12 ; J22.25 129.16,43.53 ; J22.25 130.34,42.55 ; J22.25 129.16,41.57 ; 82.69,90.18 J16.13 ; J16.13 84.14,90.18 ; J16.13 83.42,90.91 ; 27.77,11.51 J7.4 ; J7.4 28.75,12.49 ; J7.4 29.73,11.51 ; J16.4 84.14,93.38 ; J16.4 83.42,94.11 ; J16.4 82.69,93.38 ; 86.19,88.68 J16.16 ; J17.5 104.75,87.38 ; J17.5 104.75,84.82 ; J17.5 106.03,86.1 ; J17.5 103.47,86.1 ; 93.49,93.6 J16.22 ; J16.22 91.71,95.38 ; J16.22 95.27,95.38 ; J1.2 13.55,93.65 ; J1.2 12.63,92.12 ; J1.2 11.7,93.65 ; J1.2 12.63,95.18 ; 80.35,87.92 J16.20 ; J16.20 80.35,91.48 ; J16.20 82.12,89.7 ; 117.86,11.9 J10.12 ; J10.12 118.8,13.29 ; J10.12 118.8,10.52 ; J10.12 119.74,11.9 ; 97.97,86.1 J17.8 ; J17.8 99.25,87.38 ; J17.8 100.53,86.1 ; J17.8 99.25,84.82 ; J16.21 95.27,89.7 ; J16.21 91.71,89.7 ; J16.21 93.49,91.48 ; J16.21 93.49,87.92 ; 8.3,100.9 J1.1 ; J1.1 9.65,100.9 ; J1.1 8.98,99.52 ; J17.4 102.68,86.6 ; J17.4 102,87.27 ; J17.4 102,85.92 ; J17.4 101.32,86.6 ; SS3.1 79.3,30.33 ; SS3.1 76.02,27.05 ; SS3.1 79.3,23.77 ; SS3.1 82.57,27.05 ; SS4.1 82.57,73.05 ; SS4.1 79.3,76.33 ; SS4.1 76.02,73.05 ; 13.3,69.77 SS1.1
  GND02 w0.381: J16.16 87.64,88.68 ; J16.16 86.92,89.41 ; J16.16 86.19,88.68 ; 91.71,89.7 J16.21 ; J16.21 93.49,91.48 ; J16.21 93.49,87.92 ; J16.21 95.27,89.7 ; 8.98,99.52 J1.1 ; J1.1 8.98,102.28 ; J1.1 9.65,100.9 ; J1.1 8.3,100.9 ; J16.19 80.35,97.16 ; J16.19 82.12,95.38 ; J16.19 78.57,95.38 ; J16.19 80.35,93.6 ; SS1.1 16.07,73.05 ; SS1.1 10.52,73.05 ; SS1.1 13.3,70.27 ; SS1.1 13.3,75.83 ; 95.7,24.17 SS6.1 ; SS6.1 92.93,26.95 ; SS6.1 95.7,29.73 ; SS6.1 98.48,26.95 ; J9.5 42.36,13.05 ; J9.5 41.28,14.13 ; J9.5 40.21,13.05 ; J9.5 41.28,11.97 ; J1.3 17.92,95.18 ; J1.3 18.85,93.65 ; J1.3 17.92,92.12 ; J1.3 17,93.65 ; 10.52,27.05 SS2.1 ; SS2.1 13.3,29.83 ; SS2.1 13.3,24.27 ; SS2.1 16.07,27.05 ; J16.7 86.92,92.61 ; J16.7 86.19,91.88 ; J16.7 87.64,91.88 ; J16.7 86.92,91.15 ; J16.22 93.49,97.16 ; J16.22 95.27,95.38 ; J16.22 93.49,93.6 ; J16.22 91.71,95.38 ; 18.1,100.9 J1.5 ; J1.5 18.77,99.52 ; J1.5 18.77,102.28 ; J1.5 19.45,100.9 ; 97.97,86.1 J17.8 ; J17.8 100.53,86.1 ; J17.8 99.25,87.38 ; J17.8 99.25,84.82 ; 83.42,92.65 J16.4 ; J16.4 82.69,93.38 ; J16.4 84.14,93.38 ; J16.4 83.42,94.11 ; 78.57,89.7 J16.20 ; J16.20 82.12,89.7 ; J16.20 80.35,91.48 ; J16.20 80.35,87.92 ; J17.5 106.03,86.1 ; J17.5 103.47,86.1 ; J17.5 104.75,87.38 ; J17.5 104.75,84.82 ; SS5.1 119.9,29.73 ; SS5.1 117.13,26.95 ; SS5.1 119.9,24.17 ; SS5.1 122.68,26.95 ; 11.7,93.65 J1.2 ; J1.2 12.63,95.18 ; J1.2 12.63,92.12 ; J1.2 13.55,93.65 ; J9.2 53.79,13.05 ; J9.2 52.71,11.97 ; J9.2 52.71,14.13 ; J9.2 51.64,13.05 ; J16.13 84.14,90.18 ; J16.13 83.42,89.45 ; J16.13 82.69,90.18 ; J16.13 83.42,90.91 ; J2.2 24.74,87.53 ; J2.2 24.74,86.13 ; J2.2 25.44,86.83 ; J2.2 24.04,86.83 ; SS3.1 79.3,29.83 ; SS3.1 76.52,27.05 ; SS3.1 79.3,24.27 ; SS3.1 82.07,27.05 ; J17.7 100.53,93.1 ; J17.7 99.25,91.82 ; J17.7 97.97,93.1 ; J17.7 99.25,94.38 ; 104.75,91.82 J17.6 ; J17.6 106.03,93.1 ; J17.6 103.47,93.1 ; J17.6 104.75,94.38 ; 101.32,86.6 J17.4 ; J17.4 102,87.27 ; J17.4 102,85.92 ; J17.4 102.68,86.6 ; J8.2 18.57,85.21 ; J8.2 17.94,85.83 ; J8.2 17.94,84.58 ; SS4.1 82.07,73.05 ; SS4.1 76.52,73.05 ; SS4.1 79.3,75.83 ; SS4.1 79.3,70.27 ; J7.4 29.73,11.51 ; J7.4 28.75,10.53 ; J7.4 28.75,12.49 ; J7.4 27.77,11.51
  GND02 w0.762: J15.10 107.94,87.75
  ART03 w0.152: v1(45.85,68.32) 45.46,67.94 34.68,67.94 34.42,68.2 34.78,68.56 34.78,69.72 v1(34.16,70.34) ; v1(53.62,23.44) 52.86,24.21 51.26,24.21 v1(50.29,23.24) 49.38,24.15 47.19,24.15 v1(46.46,23.42) ; v1(129.67,67.69) 129.67,66.52 128.85,65.71 128.35,65.71 v1(127.89,66.17) ; v1(25.53,61.85) 25.11,61.85 23.01,63.94 21.25,63.94 20.99,64.21 20.99,65.68 20.62,66.04 ; v1(57.31,19.56) 57.92,20.17 59.73,20.17 v1(60.47,19.43) ; v1(124.08,60.32) 124.08,59.87 ; v1(80.9,20.19) 83.74,20.19 85.01,21.46 89.41,21.46 v1(90.17,20.7) ; v1(91.95,20.7) 92.89,19.76 98.76,19.76 99.85,20.85 v1(99.85,21.08) ; v1(105.54,64.26) 109.76,64.26 109.98,64.48 118.14,64.48 v1(118.87,63.75) ; v1(127.89,73.66) 128.27,74.04 v1(129.67,74.04) ; 71.19,86.41 v1(71.27,86.49) ; 123.06,59.87 v1(123.06,60.32) ; v1(38.68,24.13) 38.71,24.15 v1(40.94,24.15) ; v1(0.76,77.09) v1(0.76,76.07) v1(0.76,75.05) v1(0.76,74.04) v1(0.76,73.02) v1(0.76,70.1) v1(0.76,66.29) v1(0.76,62.48) v1(0.76,60.67) v1(0.76,59.67) v1(0.76,58.67) v1(0.76,57.67) v1(0.76,56.67) v1(0.76,55.67) v1(0.76,54.67) v1(0.76,51.05) v1(0.76,47.24) v1(0.76,43.43) v1(0.76,39.62) ; v1(45.59,84.71) 43.56,82.68 v1(43.43,82.68)
  ART03 w0.254: 102.88,30.44 103.24,30.08 114.5,30.08 117.06,32.64 v1(117.98,32.64) ; v1(61.85,86.36) 68.82,86.36 68.87,86.41 v1(68.91,86.41) 71.19,86.41
  ART03 w0.305: v1(118.87,63.75) 119.89,64.77 v1(123.06,64.77) v1(124.08,64.77) 125.93,64.77 127.33,66.17 v1(127.89,66.17) ; v1(31.11,55.12) v1(26.29,55.12) v1(23.37,55.12) 21.21,55.12 v1(20.45,55.88) v1(18.92,55.88) 17.91,56.89 17.91,64.29 ; v1(31.11,55.12) v1(33.4,55.12) 33.41,55.12 v1(35.02,55.12) 35.02,55.12 v1(36.32,55.12) v1(37.72,55.12) v1(40.51,55.12) v1(42.42,55.12) v1(44.96,55.12) 46.61,55.12 v1(47.24,55.75) 47.8,56.31 v1(47.8,56.59) 47.83,56.56 v1(49.43,56.56) 49.91,56.08 v1(49.91,55.75) v1(51.44,55.75) 73.87,55.75 v1(73.94,55.68) 75.84,53.78 98.17,53.78 v1(98.2,53.82) 98.23,53.78 v1(103.82,53.78) 104.27,53.33 116.08,53.33 v1(119.25,50.16) v1(120.52,50.16) 121.3,49.39 122.67,49.39 v1(122.81,49.53) 123.17,49.89 123.17,50.78 v1(123.32,50.93) 123.35,50.9 v1(125.22,50.9) v1(125.22,52.7) ; v1(31.11,55.12) v1(31.11,53.59) 30.9,53.37 30.9,52.03 v1(31.11,51.81) 33.15,49.78 v1(35.94,49.78) 43.69,49.78 v1(44.33,50.42) v1(45.59,50.42) v1(61.47,50.42) 63.75,50.42 v1(64.26,49.91) 64.45,49.72 v1(68.5,49.72) 69.99,49.72 v1(72.39,47.32) 72.95,46.76 77.23,46.76 77.71,47.24 v1(79.12,47.24) v1(87,47.24) v1(91.57,47.24) 91.95,47.62 v1(92.96,47.62) v1(94.49,47.62) 95.17,46.94 98.76,46.94 99.15,47.33 ; v1(125.22,52.7) 125.86,53.34 v1(127.64,53.34) v1(128.65,53.34) 129.26,52.73 v1(129.26,51.94) 129.26,48.49 v1(128.91,48.13) 128.91,47.63 127.85,46.58 125.32,46.58 v1(124.59,45.85) 124.59,45.59 v1(123.95,44.96) 123.95,43.98 123.59,43.62 121.36,43.62 v1(120.78,44.19) 119.38,44.19 115.97,47.61 v1(112.27,47.61) ; v1(125.22,52.7) 125.22,57.32 124.92,57.63 122.57,57.63 121.78,58.42 118.76,58.42 v1(117.87,59.31) 117.23,58.67 v1(115.44,58.67) 114.84,58.07 112.61,58.07 v1(112.01,58.67) v1(110.87,58.67) v1(109.86,58.67) v1(107.44,58.67) v1(106.3,58.67) 105.28,59.69 v1(105.28,60.07) v1(104.39,60.96) 103.87,60.43 95.12,60.43 94.66,60.9 ; v1(98.3,64.27) 98.8,64.27 99.47,63.6 102.08,63.6 v1(102.74,64.26) v1(105.54,64.26) ; 94.66,60.9 87.02,60.9 86.73,61.19 v1(73.43,61.19) 73.29,61.05 60.55,61.05 v1(59.5,62.1) 59.5,62.1 v1(55.02,62.1) 54.96,62.16 v1(49.57,62.16) 49.4,62 44.75,62 v1(43.05,60.3) 27.46,60.3 v1(27.43,60.32) 25.78,60.32 25.32,60.78 25.32,61.64 v1(25.53,61.85) ; 94.66,60.9 95.56,61.81 95.56,64.19 v1(95.63,64.26) ; v1(127.89,73.66) 126.82,73.66 124.65,71.49 123.23,71.49 122.75,71.02 95.41,71.02 v1(95.28,70.89) 93.75,70.89 v1(93.73,70.86) 88.99,70.86 88.65,70.52 v1(88.65,68.71) v1(88.65,67.41) 79.44,67.41 v1(79.44,67.41) 76,67.41 v1(75.97,67.39) ; v1(49.4,68.96) v1(48.13,68.96) 46.48,68.96 v1(45.85,68.32) ; 27.62,71.61 22.05,66.04 20.62,66.04 ; v1(132.24,68.15) v1(132.24,45.29)
  ART03 w0.381: v1(128.27,24.38) v1(128.27,26.41) v1(128.27,28.57) 128.27,28.95 v1(127.64,29.59)
  ART03 w0.508: SS1.1 12.12,74.23 12.12,82.67 12.88,83.44 14.32,83.44 14.86,82.9 v1(14.86,82.29) ; v1(129.67,67.69) v1(129.67,69.21) v1(129.67,70.74) v1(129.67,72.26) v1(129.67,74.04) v1(129.67,75.56) v1(129.67,77.4) v1(129.67,78.74) v1(129.67,80.26) v1(129.67,82.07) 126.46,82.07 122.96,78.57 118.84,78.57 117.99,77.72 v1(116.2,77.72) v1(114.17,77.72) 114.17,77.72 v1(112.01,77.72) v1(110.62,77.72) v1(108.46,77.72) 108.45,77.72 v1(106,77.72) v1(102.8,77.72) 90.04,77.72 v1(89.98,77.78) 89.31,78.45 v1(82.68,78.45) 80.04,78.45 79.67,78.08 66.3,78.08 65.71,78.68 ; v1(60.47,19.43) 61.23,20.19 v1(72.9,20.19) v1(75.56,20.19) v1(80.9,20.19) ; 34.42,68.2 26.98,68.2 26.44,67.66 v1(26.44,65) 26.14,64.69 26.14,63.86 26.27,63.73 26.27,62.59 v1(25.53,61.85) ; v1(95.63,64.26) 95.64,64.27 v1(98.3,64.27) ; v1(34.16,70.34) 32.26,72.24 v1(32.26,72.64) ; 33.89,76.96 v1(41.66,76.96) 41.99,76.63 46.79,76.63 v1(47.37,77.21) 47.61,76.97 v1(52.88,76.97) 57.42,76.97 59.97,79.53 ; 9.53,35.41 7.49,33.37 7.49,32.05 ; v1(112.27,47.61) v1(111.27,47.61) v1(110.27,47.61) v1(109.27,47.61) v1(108.27,47.61) v1(107.27,47.61) v1(106.27,47.61) v1(105.27,47.61) v1(104.27,47.61) 99.43,47.61 v1(99.31,47.5) 99.15,47.33 ; v1(132.24,94.82) v1(132.24,91.01) v1(132.24,87.2) v1(132.24,83.39) v1(132.24,79.58) v1(132.24,75.77) v1(132.24,71.96) v1(132.24,68.15) ; 70.72,24.64 v1(70.35,25) 69.86,25 69.35,25.51 v1(69.35,26.85) v1(67.28,26.85) 66.7,27.43 61.74,27.43 v1(61.08,26.77) v1(60.08,26.77) v1(59.08,26.77) v1(58.08,26.77) v1(57.08,26.77) v1(56.08,26.77) v1(55.08,26.77) 54.91,26.6 v1(53.08,26.6) 53.08,26.62 52.52,27.18 51.37,27.18 50.81,26.62 v1(50.81,26.6) 50.73,26.51 v1(48.79,26.51) v1(47.79,26.51) v1(46.79,26.51) v1(44.79,26.51) v1(43.79,26.51) 43.69,26.41 v1(39.73,26.41) v1(37.21,26.41) v1(35.61,26.41) 34.99,26.41 34.34,25.76 33.06,25.76 32.26,24.96 v1(32.26,23.62) 32.5,23.38 32.5,22.27 31.66,21.43 30.97,21.43 30.47,21.93 30.47,23.23 v1(30.86,23.62) 28.92,23.62 28.41,24.13 v1(28.41,26.62) 28.41,29.58 v1(29.57,30.74) 35.95,30.74 v1(36.07,30.86) 43.07,30.86 v1(43.45,30.48) v1(48.15,30.48) v1(51.94,30.48) 63.32,30.48 v1(63.35,30.45) 65.53,32.64 v1(78.36,32.64) v1(86.36,32.64) v1(94.23,32.64) v1(98.42,32.64) v1(99.82,32.64) 100.68,32.64 102.88,30.44 ; 70.72,24.64 70.35,24.27 v1(70.35,24) v1(69.35,24) 69.3,24.05 v1(63.93,24.05) 63.32,23.44 v1(55.62,23.44) v1(54.62,23.44) v1(53.62,23.44) ; 70.72,24.64 v1(74.68,24.64) 75.56,25.53 v1(75.56,29.08) 77.27,29.08 SS3.1 81.33,29.08 v1(87.25,29.08) v1(91.06,29.08) 93.57,29.08 SS6.1 96.11,26.54 v1(102.74,26.54) v1(103.89,26.54) v1(105.16,26.54) v1(106.43,26.54) v1(107.7,26.54) v1(108.97,26.54) v1(111.25,26.54) v1(112.52,26.54) v1(113.79,26.54) 119.49,26.54 SS5.1 120.28,27.33 124.23,27.33 v1(124.71,27.81) 125.86,27.81 v1(127.64,29.59) 127.95,29.59 128,29.54 128.54,29.54 128.59,29.59 v1(128.91,29.59) 129.03,29.72 v1(129.03,31.37) 129.02,31.37 128.75,31.63 126.35,31.63 v1(125.09,32.89) v1(124.08,32.89) 121.03,32.89 v1(120.78,32.64) v1(117.98,32.64) ; v1(128.27,24.38) 128.27,24.38 v1(127.64,23.75) 127.26,23.75 v1(125.22,21.72) 124.84,21.33 106.08,21.33 v1(105.38,20.64) 104.94,21.08 v1(99.85,21.08) ; v1(40.94,24.15) 45.72,24.15 v1(46.46,23.42) ; 17.91,64.29 17.91,64.51 v1(18.54,65.15) 19.43,66.04 20.62,66.04 ; v1(90.17,20.7) v1(91.95,20.7) ; v1(57.31,19.56) v1(56.31,19.56) 55.67,18.92 42.04,18.92 v1(40.51,20.45) 40.18,20.12 35.89,20.12 v1(35.56,20.45) 35.07,19.96 34.58,19.96 34.06,20.47 34.06,22.1 v1(34.29,22.33) 34.29,23.62 34.8,24.13 v1(38.68,24.13) ; v1(0.76,35.81) v1(0.76,39.62)
  ART03 w0.533: 18.77,99.52 J1.5 ; J1.5 19.45,100.9 ; J1.5 18.1,100.9 ; 93.49,93.6 J16.22 91.71,95.38 ; 93.49,87.92 J16.21 ; J16.21 91.71,89.7 ; J16.21 93.49,91.48 ; J16.21 95.27,89.7 ; 83.42,89.45 J16.13 ; J16.13 83.42,90.91 ; J16.13 82.69,90.18 ; J16.13 84.14,90.18 ; J16.16 86.92,89.41 ; J16.16 87.64,88.68 ; J16.16 86.19,88.68 ; J8.2 17.94,85.83 ; SS2.1 16.07,27.05 ; SS2.1 13.3,24.27 ; SS2.1 13.3,29.83 ; J17.8 100.53,86.1 ; J17.8 99.25,84.82 ; J17.8 97.97,86.1 ; J17.8 99.25,87.38 ; 83.42,92.65 J16.4 ; J16.4 84.14,93.38 ; J16.4 82.69,93.38 ; J16.4 83.42,94.11 ; J9.5 42.36,13.05 ; J9.5 40.21,13.05 ; J9.5 41.28,11.97 ; J9.5 41.28,14.13 ; 78.57,89.7 J16.20 ; J16.20 80.35,91.48 ; J16.20 82.12,89.7 ; J16.20 80.35,87.92 ; 12.63,92.12 J1.2 ; J1.2 11.7,93.65 ; J1.2 13.55,93.65 ; J1.2 12.63,95.18 ; 28.75,10.53 J7.4 ; J7.4 29.73,11.51 ; J7.4 28.75,12.49 ; J7.4 27.77,11.51 ; 51.64,13.05 J9.2 ; J9.2 52.71,11.97 ; J9.2 53.79,13.05 ; J9.2 52.71,14.13 ; 13.3,70.27 SS1.1 ; SS1.1 13.3,75.83 ; SS1.1 16.07,73.05 ; 86.19,91.88 J16.7 ; J16.7 87.64,91.88 ; J16.7 86.92,92.61 ; J16.7 86.92,91.15 ; 80.35,93.6 J16.19 ; J16.19 78.57,95.38 ; J16.19 82.12,95.38 ; 104.75,91.82 J17.6 ; J17.6 106.03,93.1 ; J17.6 103.47,93.1 ; 8.3,100.9 J1.1 ; J1.1 8.98,99.52 ; J1.1 9.65,100.9 ; 101.32,86.6 J17.4 ; J17.4 102.68,86.6 ; J17.4 102,87.27 ; J17.4 102,85.92 ; 103.47,86.1 J17.5 ; J17.5 106.03,86.1 ; J17.5 104.75,87.38 ; J17.5 104.75,84.82 ; J1.3 17.92,95.18 ; J1.3 18.85,93.65 ; J1.3 17,93.65 ; J17.7 100.53,93.1 ; J17.7 97.97,93.1 ; J17.7 99.25,91.82
  PWR04 w0.533: 8.3,100.9 J1.1 ; J1.1 9.65,100.9 ; J1.1 8.98,99.52 ; 52.71,11.97 J9.2 ; 28.75,10.53 J7.4 ; J7.4 29.73,11.51 ; J7.4 27.77,11.51 ; 18.77,99.52 J1.5 ; J1.5 19.45,100.9 ; J1.5 18.1,100.9 ; J17.6 106.03,93.1 ; J1.2 12.63,95.18 ; 41.28,11.97 J9.5 ; J1.3 17.92,95.18
  GND05 w0.381: J1.2 12.63,95.18 ; J1.2 11.7,93.65 ; J1.2 12.63,92.12 ; J1.2 13.55,93.65 ; J1.3 17.92,95.18 ; J1.3 17.92,92.12 ; J1.3 17,93.65 ; J1.3 18.85,93.65 ; 13.3,24.27 SS2.1 ; SS2.1 13.3,29.83 ; SS2.1 16.07,27.05 ; SS2.1 10.52,27.05 ; 82.69,90.18 J16.13 ; J16.13 83.42,89.45 ; J16.13 83.42,90.91 ; J16.13 84.14,90.18 ; 13.3,70.27 SS1.1 ; SS1.1 16.07,73.05 ; SS1.1 13.3,75.83 ; SS1.1 10.52,73.05 ; J7.4 29.73,11.51 ; J7.4 28.75,10.53 ; J7.4 28.75,12.49 ; J7.4 27.77,11.51 ; 86.19,88.68 J16.16 ; J16.16 87.64,88.68 ; J16.16 86.92,89.41 ; J9.5 41.28,14.13 ; J9.5 42.36,13.05 ; J9.5 41.28,11.97 ; J9.5 40.21,13.05 ; J16.19 82.12,95.38 ; J16.19 80.35,93.6 ; J16.19 78.57,95.38 ; J16.19 80.35,97.16 ; 80.35,87.92 J16.20 ; J16.20 80.35,91.48 ; J16.20 82.12,89.7 ; J16.20 78.57,89.7 ; J17.4 102,87.27 ; J17.4 102,85.92 ; J17.4 102.68,86.6 ; J17.4 101.32,86.6 ; J17.8 99.25,87.38 ; J17.8 100.53,86.1 ; J17.8 97.97,86.1 ; J17.8 99.25,84.82 ; J17.7 99.25,94.38 ; J17.7 97.97,93.1 ; J17.7 100.53,93.1 ; J17.7 99.25,91.82 ; J16.7 87.64,91.88 ; J16.7 86.92,92.61 ; J16.7 86.19,91.88 ; J16.7 86.92,91.15 ; J16.4 83.42,94.11 ; J16.4 83.42,92.65 ; J16.4 82.69,93.38 ; J16.4 84.14,93.38 ; 18.1,100.9 J1.5 ; J1.5 19.45,100.9 ; J1.5 18.77,99.52 ; J1.5 18.77,102.28 ; J16.21 95.27,89.7 ; J16.21 93.49,87.92 ; J16.21 93.49,91.48 ; J16.21 91.71,89.7 ; J17.5 106.03,86.1 ; J17.5 104.75,87.38 ; J17.5 103.47,86.1 ; J17.5 104.75,84.82 ; 95.7,24.17 SS6.1 ; SS6.1 92.93,26.95 ; SS6.1 98.48,26.95 ; SS6.1 95.7,29.73 ; J8.2 18.57,85.21 ; J8.2 17.94,84.58 ; J8.2 17.94,85.83 ; J16.22 95.27,95.38 ; J16.22 93.49,93.6 ; J16.22 91.71,95.38 ; J16.22 93.49,97.16 ; 76.52,73.05 SS4.1 ; SS4.1 82.07,73.05 ; SS4.1 79.3,70.27 ; SS4.1 79.3,75.83 ; 76.52,27.05 SS3.1 ; SS3.1 79.3,24.27 ; SS3.1 82.07,27.05 ; SS3.1 79.3,29.83 ; J1.1 8.98,102.28 ; J1.1 8.98,99.52 ; J1.1 9.65,100.9 ; J1.1 8.3,100.9 ; 119.9,24.17 SS5.1 ; SS5.1 119.9,29.73 ; SS5.1 122.68,26.95 ; SS5.1 117.13,26.95 ; 52.71,11.97 J9.2 ; J9.2 51.64,13.05 ; J9.2 52.71,14.13 ; J9.2 53.79,13.05 ; J2.2 25.44,86.83 ; J2.2 24.74,86.13 ; J2.2 24.74,87.53 ; J2.2 24.04,86.83 ; 104.75,91.82 J17.6 ; J17.6 106.03,93.1 ; J17.6 104.75,94.38 ; J17.6 103.47,93.1
  GND05 w0.762: J15.10 107.82,87.75
  BOTTOM w0.152: 93.19,64.68 95.21,64.68 v1(95.63,64.26) ; C186.2 47.24,93.99 47.24,86.23 v1(47.12,86.1) ; v1(99.31,80.64) 99.31,79.97 101.56,77.72 v1(102.8,77.72) ; v1(106.3,58.67) 103.78,61.19 91.37,61.19 90.7,60.52 90.7,59.92 91.19,59.43 v1(91.19,59.05) 91.52,59.05 92,59.54 96.93,59.54 97.64,60.25 102.92,60.25 105.83,57.34 110.07,57.34 110.87,58.14 v1(110.87,58.67) ; v1(73.03,85.09) 71.27,83.34 69.86,83.34 v1(68.99,82.46) 67.73,81.2 65.39,81.2 64.62,80.43 ; 73,73.4 71.37,73.4 70.87,72.9 70.87,70.74 70.31,70.18 65.46,70.18 65.15,69.87 65.15,53.47 66.5,52.12 94.69,52.12 v1(96.65,50.16) v1(99.31,47.5) v1(99.31,44.96) ; v1(62.99,42.29) 62.84,42.14 61.04,42.14 58.72,44.45 58.72,51.36 60.33,52.96 60.33,55.72 61.11,56.5 61.11,71.06 60.71,71.47 60.71,72.87 60.81,72.97 60.81,74.37 60.71,74.47 ; C24.2 v1(11.81,62.36) ; 114,83.25 113.08,82.33 113.08,76.16 ; C55.2 v1(38.62,41.9) ; v1(75.44,57.02) 75.95,56.51 77.59,56.51 78.11,57.02 ; v1(80.14,58.55) 81.28,58.55 81.66,58.16 81.66,57.71 v1(81.76,57.61) ; 12.42,76.34 10.48,74.4 10.48,71.96 11,71.44 11,71.21 11.18,71.03 11.18,69.97 ; v1(81.41,80.9) 82.04,80.26 82.8,80.26 83.1,80.56 83.1,83.84 83.01,83.93 83.01,84.76 v1(81.15,86.61) 80.65,87.12 78.61,87.12 ; v1(52.96,72.39) 52.83,72.39 52.45,72.77 C187.2 ; 71.25,85.58 70.17,84.5 69.15,84.5 67.07,82.42 v1(65.79,82.42) ; 8.43,71.34 9.07,70.7 9.07,69.31 ; v1(118.87,63.75) v1(118.87,60.32) 118.87,58.8 113.79,53.72 103.89,53.72 v1(103.82,53.78) 102.87,54.74 102.87,55.24 102.23,55.88 v1(102.23,56.39) 102.87,56.39 104.65,54.61 112.78,54.61 117.48,59.31 v1(117.87,59.31) 117.86,59.32 117.86,63.93 117.55,64.24 116.61,64.24 115.95,64.9 114.3,64.9 113.95,65.25 v1(113.95,66.01) ; v1(98.68,68.32) 98.48,68.53 98.48,75.68 ; 36.17,84.94 36.17,85.34 ; R4.2 25.52,39.77 C4.2 ; 8.89,75.61 8.59,75.3 8.59,71.54 ; 99.72,76.49 96.88,79.34 96.88,84.72 ; 30.66,83.45 33.07,85.86 33.07,87.52 32.84,87.74 31.45,87.74 30.99,87.29 ; 110.48,81.97 110.48,82.45 ; v1(43.81,94.36) 43.81,94.23 46.58,91.46 46.58,86.8 ; C31.2 v1(17.14,27.68)
  BOTTOM w0.178: U33.4 U33.29
  BOTTOM w0.203: J24.21 v1(127.64,23.75) ; v1(113.79,31.49) 113.92,31.37 U32.2 ; Z8.1 51.43,80.21 v1(51.15,80.48) 51.15,81.25 52.15,82.24 53.26,82.24 53.47,82.45 53.47,85.72 v1(53.09,86.1) ; v1(47.37,74.67) 48.39,75.69 49.92,75.69 C188.2 ; v1(47.37,79.75) Z11.1 ; v1(45.85,68.32) U33.18 47.98,68.32 48.13,68.48 v1(48.13,68.96) ; v1(39.07,81.3) 39.75,80.62 39.75,77.34 ; v1(48.13,67.69) 47.87,67.43 U33.13 47.87,65.59 v1(47.59,65.31) 44.76,62.48 v1(44.32,62.48)
  BOTTOM w0.254: v1(95.63,64.26) 95.76,64.39 U18.3 U18.8 98.17,64.39 98.3,64.26 v1(98.3,64.27) ; 42.91,50.29 41.66,50.29 41.55,50.18 41.55,50.18 41.2,49.84 41.2,49.84 41.15,49.78 41.15,47.55 40.84,47.24 35.81,47.24 v1(35.05,46.48) 34.26,45.69 34.26,42.65 32,40.38 32,33.78 v1(33.15,32.64) ; 42.91,50.29 44.2,50.29 v1(44.33,50.42) U9.15 44.33,46.99 ; 42.91,50.29 42.42,49.8 42.42,46.73 v1(42.16,46.48) 41.91,46.23 36.57,46.23 35.15,44.81 35.15,42.14 32.87,39.85 32.87,35.3 v1(33.12,35.05) 36.83,35.05 37.08,34.8 37.08,26.54 v1(37.21,26.41) 37.21,15.75 36.17,14.71 36.17,12.22 36.58,11.81 40.62,11.81 41.28,12.47 J9.5 ; C186.2 47.79,94.11 v1(47.8,94.11) ; v1(2.67,52.07) 3.17,52.07 3.43,52.32 R7.2 ; v1(88.95,86.38) 88.9,86.33 U16.3 U16.8 ; R40.2 v1(7.37,19.05) ; v1(99.82,32.64) v1(99.82,35.18) v1(99.82,38.23) 99.82,44.45 v1(99.31,44.96) ; 78.61,87.12 78.16,86.66 78.16,84.82 76.37,83.03 74.55,83.03 73.93,82.4 v1(73.93,82.19) 73.91,82.18 73.54,82.18 69.57,78.21 ; J19.19 v1(127.89,72.24) ; 44.33,46.99 42.29,44.96 v1(42.11,44.96) v1(38.61,44.96) 37.34,44.96 37.34,40.13 39.12,38.35 D10.1 ; 44.33,46.99 45.35,45.97 46.35,45.97 C53.2 ; v1(61.47,50.42) 63.25,52.2 63.25,72.15 62.99,72.4 ; v1(127.89,73.66) 127.8,73.74 J19.16 125.77,73.74 v1(125.35,74.17) ; 44.96,22.48 44.96,18.19 47.73,15.42 47.73,12.34 48.39,11.68 51.35,11.68 J9.2 52.71,15.86 46.25,22.33 ; v1(103.89,26.54) v1(102.74,26.54) ; v1(68.2,95.12) 68.58,95.12 69.15,95.69 Q10.2 ; U17.8 U17.3 v1(84.45,86.36) 84.45,86.87 v1(83.95,87.37) ; v1(99.31,80.64) 99.31,82.29 99.82,82.8 101.46,82.8 v1(102.23,82.03) ; R42.2 v1(13.72,19.05) ; J21.18 127.23,52.75 127.48,53 127.48,53.19 v1(127.64,53.34) ; v1(81.41,80.9) 81.29,81.02 R176.2 ; J19.25 v1(127.89,69.24) ; Z10.1 v1(44.7,86.74) ; v1(79.12,47.24) 79.12,50.04 79.53,50.44 80.62,50.44 v1(81.15,49.91) 81.66,50.42 R73.2 ; v1(106.51,66.24) 106.55,66.28 C75.2 105.64,66.81 Y2.2 105.27,67.09 104.4,66.22 103.14,66.22 102.8,66.56 v1(102.8,68.32) v1(102.8,69.47) Y2.4 103.77,69.52 104.66,70.4 105.99,70.4 C74.2 106.93,69.47 v1(107.31,69.47) ; J19.28 v1(127.89,67.74) ; Z9.1 v1(45.09,95.88) ; v1(116.46,72.64) 116.71,72.39 C78.2 ; v1(36.45,97.92) U37.3 U37.8 v1(36.45,95.49) ; R41.2 v1(10.67,19.05) ; R218.2 v1(47.37,77.21) ; 129.29,61.33 v1(129.29,61.34) ; R9.2 C18.1 v1(2.67,56) ; J19.22 v1(127.89,70.74)
  BOTTOM w0.305: U6.3 29.71,16.37 v1(29.72,16.38) ; v1(93.85,72.39) 93.84,72.38 C112.2 ; v1(24.13,16.38) 24.12,16.37 U5.3 ; R102.2 v1(102.74,64.26) ; v1(91.95,20.7) 91.95,20.57 ; Z3.2 v1(23.74,14.3) ; v1(23.24,69.47) U39.9 21.44,69.47 ; Z4.2 v1(26.3,14.3) ; U5.1 24.11,17.67 v1(24.13,17.65) ; R92.2 v1(112.01,58.67) ; U39.8 21.33,68.97 ; R86.2 v1(107.82,75.18) ; v1(28.32,19.81) 28.31,19.8 C42.2 ; C153.2 v1(115.44,34.8) ; R91.2 v1(115.44,58.67) ; U6.1 29.7,17.67 v1(29.72,17.66) ; v1(102.72,62.89) 102.79,62.89 103.02,63.12 R103.2 ; R98.2 v1(102.74,65.53) ; C154.2 v1(116.71,34.8) ; C83.2 v1(112.65,75.18) ; R83.2 v1(110.87,58.67) ; C89.2 v1(114.43,75.18) ; C155.2 v1(114.17,34.8) ; C84.2 v1(110.49,75.18) ; v1(88.95,87.48) v1(88.95,86.38) ; C88.2 v1(108.84,75.18)
  BOTTOM w0.381: v1(118.4,72.64) 118.75,72.29 C158.2 ; C169.2 C168.2 45.08,65.67 v1(45.09,65.66) ; C102.1 93.73,65.91 v1(95.63,65.91) 96.51,66.79 Y3.2 97.54,68.2 v1(97.54,68.32) v1(97.54,69.49) 97.54,70.36 97.16,70.74 96.14,70.74 95.01,69.61 Y3.4 94.64,69.84 C103.2 v1(93.73,70.86) ; v1(103.25,72.39) 103.38,72.26 103.77,72.26 C86.2 ; R215.1 v1(36.45,81.28) ; v1(105.54,75.18) 106.31,74.41 C160.2 ; C47.2 v1(11.56,12.82) ; v1(105.79,72.39) 106.18,72 C85.2 ; C46.2 v1(14.61,10.03) ; C48.2 v1(10.54,12.83) ; R211.1 v1(43.43,81.28) ; D34.1 72.09,88.97 v1(72.09,88.67) ; v1(55.02,62.1) 55.02,62.25 55.24,62.47 C174.2 C175.2 ; R234.1 43.31,71.63 43.32,71.62 C180.2 C181.2 43.32,68.71 C167.2 C166.2 44.84,68.7 45.21,68.32 v1(45.85,68.32)
  BOTTOM w0.508: U12.2 v1(72.39,47.32) ; 91.18,73.78 v1(91.19,73.79) ; U12.8 71.12,42.74 v1(70.67,42.29) ; R219.2 v1(44.7,99.82) ; 50.49,28.45 50.49,53.62 50.29,53.82 50.29,53.85 49.91,54.23 v1(49.91,55.75) ; U13.8 v1(62.99,42.29) ; v1(75.44,57.02) 74.65,57.02 73,58.67 73,74.78 78.08,79.86 80.37,79.86 v1(81.41,80.9) ; v1(53.34,38.35) v1(53.34,45.01) 53.34,57.32 52.22,58.44 50.27,58.44 v1(49.47,59.24) ; v1(80.14,58.55) 79.45,59.23 79.45,60.43 78.93,60.43 75.89,63.47 75.89,73.95 79.05,77.12 83.6,77.12 86.36,79.88 v1(86.36,80.9) ; v1(127.64,56.89) 128.19,57.45 J22.26 129.16,58.8 v1(129.29,58.93) ; v1(84.58,80.9) 84.58,80.35 v1(82.68,78.45) 78.49,78.45 74.41,74.37 74.41,62.69 77.6,59.51 77.6,57.66 78.11,57.15 78.11,57.02 ; C60.2 v1(87,47.24) ; 51.94,29.17 v1(51.94,30.48) v1(51.94,35.43) v1(51.94,38.35) v1(51.94,41.45) v1(51.94,45.01) 51.94,55.24 v1(51.44,55.75) ; 47.96,28.52 48.9,29.46 v1(48.9,35.43) v1(48.9,38.35) 48.9,52.96 47.24,54.61 v1(47.24,55.75) ; R72.2 v1(80.78,42.29) ; U13.2 v1(64.26,49.91) ; U11.5 v1(84.33,42.29) ; R217.2 v1(47.24,101.09) ; U10.5 v1(92.2,42.29) ; C61.2 v1(79.12,47.24) ; J15.10 108.72,87.75 ; R64.2 v1(88.65,42.29)
  BOTTOM w0.533: 51.64,13.05 J9.2 ; J9.2 52.71,11.97 ; J9.2 53.79,13.05 ; 28.75,10.53 J7.4 ; J7.4 28.75,12.49 ; J7.4 29.73,11.51 ; J7.4 27.77,11.51 ; J8.2 17.94,85.83 ; J8.2 18.57,85.21 ; J8.2 17.94,84.58 ; J16.19 82.12,95.38 ; J16.19 80.35,93.6 ; J16.19 80.35,97.16 ; 97.97,93.1 J17.7 ; J17.7 99.25,94.38 ; J17.7 100.53,93.1 ; J17.4 102.68,86.6 ; J17.4 102,87.27 ; J17.4 102,85.92 ; J17.4 101.32,86.6 ; 86.19,88.68 J16.16 ; J16.16 87.64,88.68 ; J16.16 86.92,89.41 ; J16.20 82.12,89.7 ; 103.47,93.1 J17.6 ; J17.6 104.75,94.38 ; J17.6 106.03,93.1 ; J17.6 104.75,91.82 ; J2.2 24.74,87.53 ; J2.2 24.74,86.13 ; J2.2 25.44,86.83 ; 18.77,99.52 J1.5 ; J1.5 18.1,100.9 ; J1.5 19.45,100.9 ; 129.21,63.62 J20.32 129.21,65.57 ; 127.98,20.55 J24.25 ; J24.25 130.34,20.55 ; J24.25 129.16,19.57 ; J24.25 129.16,21.53 ; 86.19,91.88 J16.7 ; J16.7 86.92,92.61 ; J16.7 87.64,91.88 ; 10.52,27.05 SS2.1 ; SS2.1 13.3,24.27 ; SS2.1 13.3,29.83 ; 104.75,84.82 J17.5 ; J17.5 103.47,86.1 ; J17.5 106.03,86.1 ; J17.5 104.75,87.38 ; J9.5 42.36,13.05 ; J9.5 41.28,14.13 ; J9.5 40.21,13.05 ; 117.5,19.54 J31.8 ; J31.8 117.5,21.99 ; J31.8 118.18,20.76 ; J1.3 17.92,95.18 ; J1.3 17,93.65 ; J1.3 18.85,93.65 ; J1.3 17.92,92.12 ; J1.2 13.55,93.65 ; J1.2 12.63,95.18 ; J1.2 11.7,93.65 ; J1.2 12.63,92.12 ; 92.93,26.95 SS6.1 ; SS6.1 98.48,26.95 ; SS6.1 95.7,24.17 ; SS6.1 95.7,29.73 ; J31.9 104.5,21.99 ; J31.9 103.82,20.76 ; J31.9 105.18,20.76 ; J31.9 104.5,19.54 ; 129.16,41.57 J22.25 ; J22.25 130.34,42.55 ; J22.25 129.16,43.53 ; J31.10 117.5,9.99 ; J31.10 118.18,8.76 ; J31.10 116.82,8.76 ; 8.98,99.52 J1.1 ; J1.1 8.3,100.9 ; J1.1 9.65,100.9 ; J16.22 93.49,97.16 ; J16.22 91.71,95.38 ; J16.22 93.49,93.6 ; J16.22 95.27,95.38 ; J20.31 130.39,83.39 ; J20.31 129.21,82.42 ; J20.31 129.21,84.37 ; SS3.1 79.3,29.83 ; SS3.1 76.52,27.05 ; SS3.1 82.07,27.05 ; SS3.1 79.3,24.27 ; 91.71,89.7 J16.21 95.27,89.7 ; 103.82,8.76 J31.11 ; J31.11 105.18,8.76 ; J31.11 104.5,9.99 ; 13.3,70.27 SS1.1 13.3,75.83 ; SS4.1 82.07,73.05 ; SS4.1 79.3,75.83 ; SS4.1 76.52,73.05 ; SS4.1 79.3,70.27 ; 127.98,35.45 J24.26 ; J24.26 130.34,35.45 ; J24.26 129.16,36.43 ; 82.69,93.38 J16.4 ; J16.4 83.42,94.11 ; J16.4 84.14,93.38 ; 82.69,90.18 J16.13 ; 99.25,84.82 J17.8 ; J17.8 99.25,87.38 ; J17.8 100.53,86.1 ; J17.8 97.97,86.1 ; 119.9,29.73 SS5.1 119.9,24.17
  vias: v1(0.84,100.58) v1(0.76,96.77) v1(0.76,93.63) v1(0.76,92.63) v1(0.76,91.63) v1(0.76,90.63) v1(0.76,89.63) v1(0.76,88.63) v1(0.76,87.63) v1(0.76,86.49) v1(0.76,85.34) v1(0.76,84.07) v1(0.76,81.53) v1(0.76,32) v1(0.76,28.19) v1(0.76,24.38) v1(0.76,20.57) v1(0.76,16.76) v1(0.76,12.95) v1(1.78,83.44) v1(1.78,81.53) v1(2.03,93.63) v1(2.03,92.63) v1(2.03,91.63) v1(2.03,90.63) v1(2.03,89.63) v1(2.03,88.63) v1(2.03,87.63) v1(2.67,59) v1(2.67,58) v1(2.67,57) v1(2.79,76.97) v1(2.79,76.07) v1(2.79,75.05) v1(2.79,74.04) v1(2.79,73.02) v1(3.03,93.63) v1(3.03,92.63) v1(3.03,91.63) v1(3.3,83.44) v1(3.3,80.9) v1(3.43,22.24) v1(3.43,17.92) v1(3.56,31) v1(3.71,35.55) v1(4.03,93.63) v1(4.03,92.63) v1(4.03,91.63) v1(4.48,7.76) v1(4.57,16.76) v1(5.03,93.63) v1(5.03,92.63) v1(5.03,91.63) v1(5.54,22.42) v1(5.59,31.13) v1(5.65,17.92) v1(5.92,68.73) v1(6.03,93.63) v1(6.03,92.63) v1(6.03,91.63) v1(5.97,51.05) v1(5.97,50.04) v1(6.33,56.64) v1(7.03,93.63) v1(7.03,92.63) v1(7.03,91.63) v1(7.03,90.63) v1(7.03,89.63) v1(7.03,88.63) v1(7.03,87.63) v1(6.99,51.05) v1(6.99,50.04) v1(6.99,43.18) v1(7.33,56.64) v1(7.37,82.87) v1(7.44,59.69) v1(7.44,58.69) v1(8.03,87.63) v1(8.03,86.63) v1(7.98,51.04) v1(7.98,50.04) v1(8,43.18) v1(8,42.18) v1(8,41.18) v1(8.08,102.24) v1(8.08,98.43) v1(8.13,24) v1(8.33,56.64) v1(8.29,11.57) v1(8.29,7.76) v1(8.44,64.69) v1(8.44,63.69) v1(8.44,62.69) v1(8.44,61.69) v1(8.44,60.69) v1(8.44,59.69) v1(8.44,58.69) v1(8.64,39.75) v1(10.39,77.93) v1(10.67,14.35) v1(11.7,97.43) v1(11.7,96.43) v1(11.81,63.36) v1(11.81,52.56) v1(11.81,51.56) v1(11.81,50.56) v1(11.81,49.56) v1(11.81,48.56) v1(11.81,47.56) v1(11.81,46.56) v1(11.81,45.56) v1(11.81,44.56) v1(11.81,43.56) v1(11.89,102.24) v1(12.06,79.25) v1(12.06,78.25) v1(12.1,7.76) v1(12.7,97.43) v1(12.7,96.43) v1(13.46,36.96) v1(13.46,36.15) v1(13.46,35.15) v1(13.46,34.15) v1(13.46,33.15) v1(13.7,97.43) v1(13.7,96.43) v1(13.72,14.35) v1(13.92,86.77) v1(14.46,37.15) v1(14.46,36.15) v1(14.46,35.15) v1(14.46,34.15) v1(14.46,33.15) v1(14.7,97.43) v1(14.7,96.43) v1(14.7,95.43) v1(14.7,94.43) v1(14.7,93.43) v1(14.92,87.77) v1(14.92,86.77) v1(14.92,85.77) v1(15.08,79.48) v1(15.08,78.48) v1(15.37,14.35) v1(15.46,37.15) v1(15.46,36.15) v1(15.46,35.15) v1(15.46,34.15) v1(15.46,33.15) v1(15.62,47.12) v1(15.62,44.07) v1(15.7,102.24) v1(15.7,98.43) v1(15.7,97.43) v1(15.7,96.43) v1(15.7,95.43) v1(15.7,94.43) v1(15.7,93.43) v1(15.92,87.77) v1(15.92,86.77) v1(15.91,7.76) v1(16.08,81.48) v1(16.08,80.48) v1(16.08,79.48) v1(16.27,12.7) v1(16.51,45.08) v1(16.51,19.81) v1(16.7,98.43) v1(16.7,97.43) v1(16.7,96.43) v1(16.76,50.04) v1(16.76,48.89) v1(17.14,30.68) v1(17.14,29.68) v1(17.14,28.68) v1(17.35,35.15) v1(17.35,34.15) v1(17.35,33.15) v1(17.43,25.49) v1(17.43,24.49) v1(17.43,23.49) v1(17.7,98.43) v1(17.7,97.43) v1(17.7,96.43) v1(18.14,30.68) v1(18.14,29.68) v1(18.21,75.08) v1(18.31,77.01) v1(18.43,25.49) v1(18.43,24.49) v1(18.43,23.49) v1(18.54,79.22) v1(18.57,59.87) v1(18.7,98.43) v1(18.7,97.43) v1(18.7,96.43) v1(18.75,63.45) v1(18.9,54.17) v1(18.9,53.17) v1(18.9,52.17) v1(18.92,50.04) v1(18.92,47.12) v1(18.92,45.08) v1(19,9.57) v1(19.14,34.38) v1(19.14,33.38) v1(19.14,32.38) v1(19.43,25.49) v1(19.43,24.49) v1(19.43,23.49) v1(19.51,102.24) v1(19.56,14.35) v1(19.7,98.43) v1(19.7,97.43) v1(19.7,96.43) v1(19.7,95.43) v1(19.68,91.95) v1(19.68,62.86) v1(19.72,7.76) v1(19.82,69.21) v1(19.89,57.86) v1(20.14,34.38) v1(20.14,33.38) v1(20.14,32.38) v1(20.19,19.81) v1(20.32,37.72) v1(20.43,25.49) v1(20.43,24.49) v1(20.45,23.49) v1(20.57,50.04) v1(20.57,47.12) v1(20.65,54.17) v1(20.65,53.17) v1(20.65,52.17) v1(20.82,69.21) v1(20.82,68.21) v1(20.95,93.85) v1(21,77.99) v1(21,76.99) v1(21,75.99) v1(21.08,100.2) v1(21.26,70.91) v1(21.46,47.12) v1(21.65,54.17) v1(21.65,53.17) v1(21.65,52.17) v1(22,77.99) v1(22.23,91.95) v1(22.2,50.06) v1(22.61,88.77) v1(22.68,95.55) v1(22.73,57.53) v1(22.79,98.55) v1(22.81,9.57) v1(22.99,24.3) v1(22.99,23.5) v1(23.11,91.95) v1(23.5,89.79) v1(23.53,7.76) v1(24,93.85) v1(24,78.99) v1(24,50.04) v1(24,43.05) v1(23.99,24.3) v1(23.99,23.5) v1(24.13,51.97) v1(24.1,47.88) v1(24.1,37.84) v1(24.64,84.71) v1(24.62,82.29) v1(24.64,57.53) v1(24.66,95.55) v1(24.77,30.74) v1(24.77,29.74) v1(24.99,24.3) v1(24.99,23.5) v1(25.15,89.79) v1(25.27,101.09) v1(25.37,98.55) v1(25.4,95.12) v1(25.79,24.3) v1(26.29,101.09) v1(26.29,57.6) v1(26.29,56.37) v1(26.29,51.81) v1(26.43,50.04) v1(26.62,9.57) v1(26.67,76.83) v1(26.92,70.56) v1(27.23,37.62) v1(27.3,47.88) v1(27.3,46.48) v1(27.3,43.05) v1(27.3,41.78) v1(27.34,7.76) v1(27.43,50.04) v1(27.56,86.36) v1(27.56,84.83) v1(27.58,51.84) v1(27.57,33.74) v1(27.57,32.74) v1(27.81,65.02) v1(27.88,92.07) v1(28.19,89.28) v1(28.32,78.23) v1(28.32,61.85) v1(28.43,50.04) v1(29.02,86.99) v1(29.08,51.81) v1(29.08,46.48) v1(29.1,41.78) v1(29.34,65.02) v1(29.43,50.04) v1(29.46,99.54) v1(29.57,31.74) v1(29.97,82.24) v1(29.97,46.48) v1(29.97,41.78) v1(29.97,19.81) v1(30.29,92.45) v1(30.41,56.37) v1(30.43,9.57) v1(30.51,90.37) v1(30.51,57.53) v1(30.48,36.45) v1(30.58,94.97) v1(30.73,101.09) v1(30.99,65.02) v1(30.99,49.15) v1(31.11,62.99) v1(31.11,14.73) v1(31.18,95.88) v1(31.15,11.57) v1(31.15,7.76) v1(31.41,56.37) v1(31.51,57.53) v1(31.62,80.64) v1(32.26,73.8) v1(32.41,56.37) v1(32.51,57.53) v1(32.89,53.59) v1(33.73,65.68) v1(33.76,57.49) v1(33.75,56.38) v1(33.91,101.22) v1(33.91,85.22) v1(33.91,36.45) v1(34.1,86.74) v1(34.46,97.94) v1(34.75,102.24) v1(34.8,78.89) v1(34.92,36.45) v1(35,56.38) v1(34.96,11.57) v1(34.96,7.76) v1(35.51,73) v1(35.53,9.57) v1(35.59,86.65) v1(35.81,94.23) v1(35.94,48.26) v1(36.25,56.42) v1(36.7,92.05) v1(37.03,22.71) v1(37.08,86.74) v1(37.06,73.02) v1(37.55,65.38) v1(37.72,92.05) v1(38.42,70.34) v1(38.48,97.15) v1(38.56,102.24) v1(38.81,62.49) v1(38.84,57.57) v1(38.77,11.57) v1(38.77,7.76) v1(39.12,85.85) v1(39.34,9.57) v1(39.75,84.58) v1(40.39,82.29) v1(40.39,81.28) v1(41.05,36.45) v1(41.66,84.58) v1(42.05,36.45) v1(42.19,23.47) v1(42.29,52.96) v1(42.37,102.24) v1(42.42,57.53) v1(42.58,11.57) v1(42.58,7.76) v1(43.05,36.45) v1(43.15,9.57) v1(43.31,62.48) v1(43.43,88.39) v1(43.69,92.58) v1(43.97,74.65) v1(43.98,71.95) v1(44.05,36.45) v1(44.27,23.37) v1(44.7,89.53) v1(44.83,57.53) v1(44.79,27.51) v1(44.96,32.75) v1(44.96,31.75) v1(45.09,81.28) v1(45.85,74.67) v1(45.85,36.45) v1(46.18,102.24) v1(46.18,98.43) v1(46.39,11.57) v1(46.39,7.76) v1(46.53,50.45) v1(46.74,83.95) v1(46.79,27.51) v1(46.79,25.51) v1(46.86,36.45) v1(46.96,9.57) v1(47.12,41.4) v1(47.5,45.03) v1(47.79,27.51) v1(47.79,25.51) v1(48.13,86.1) v1(48.13,31.75) v1(48.26,41.4) v1(49.4,67.69) v1(49.66,91.18) v1(49.66,86.1) v1(49.65,80.48) v1(49.99,102.24) v1(49.99,98.43) v1(50.2,11.57) v1(50.2,7.76) v1(50.42,32.03) v1(50.51,48.08) v1(50.55,41.4) v1(50.55,38.35) v1(50.55,35.43) v1(50.57,90.27) v1(50.67,97.41) v1(50.67,95.88) v1(50.77,9.57) v1(51.53,70.6) v1(52.65,80.48) v1(52.96,95.88) v1(52.96,94.36) v1(53.09,88.01) v1(53.34,35.43) v1(53.34,31.42) v1(53.49,84.61) v1(53.52,82.19) v1(53.8,102.24) v1(54.01,11.57) v1(54.01,7.76) v1(54.48,93.47) v1(54.58,9.57) v1(54.74,88.01) v1(55.75,95.88) v1(55.75,93.47) v1(56.13,36.45) v1(56.1,31.49) v1(56.1,30.49) v1(57.15,90.68) v1(57.1,32.49) v1(57.1,31.49) v1(57.1,30.49) v1(57.61,102.24) v1(57.61,98.43) v1(57.82,11.57) v1(57.82,7.76) v1(58.1,32.49) v1(58.1,31.49) v1(58.1,30.49) v1(58.42,88.77) v1(58.36,74.11) v1(58.41,70.49) v1(58.39,9.57) v1(58.79,60.32) v1(58.96,69.3) v1(59.05,68.16) v1(59.1,33.49) v1(59.1,32.49) v1(59.1,31.49) v1(59.1,30.49) v1(59.18,90.68) v1(59.29,63.52) v1(59.41,70.49) v1(59.66,60.01) v1(59.84,57.93) v1(60.1,30.49) v1(60.53,88.14) v1(60.45,33.53) v1(60.71,82.42) v1(61.42,102.24) v1(61.42,98.43) v1(61.59,91.06) v1(61.63,11.57) v1(61.63,7.76) v1(61.98,88.14) v1(62.1,46.38) v1(62.23,36.45) v1(62.23,35.43) v1(62.2,9.57) v1(62.48,95.12) v1(62.65,81.41) v1(63.5,36.45) v1(63.5,35.43) v1(64.26,97.15) v1(64.64,46.35) v1(64.74,79.69) v1(65.23,102.24) v1(65.23,98.43) v1(65.28,77.58) v1(65.25,76.24) v1(65.41,99.57) v1(65.43,15.54) v1(65.44,11.57) v1(65.44,7.76) v1(65.47,65.23) v1(66.01,9.57) v1(66.55,88.14) v1(66.93,96.26) v1(67.06,80.39) v1(67.06,14.35) v1(67.25,36.47) v1(67.25,35.46) v1(67.63,69.6) v1(67.82,43.56) v1(68.25,36.47) v1(68.25,35.47) v1(68.58,80.39) v1(69.04,102.24) v1(69.25,11.57) v1(69.25,7.76) v1(69.68,62.64) v1(69.82,9.57) v1(69.94,76.2) v1(69.99,57.8) v1(70.63,36.45) v1(70.63,35.43) v1(70.94,76.2) v1(71.02,30.48) v1(71.25,88.14) v1(71.17,66.06) v1(71.37,95.12) v1(71.94,76.2) v1(72.14,87.23) v1(72.85,102.24) v1(72.9,98.42) v1(73.03,71.75) v1(73.06,11.57) v1(73.06,7.76) v1(74.17,14.35) v1(74.26,80.03) v1(74.42,36.45) v1(74.42,35.43) v1(74.88,87.71) v1(75.69,36.45) v1(75.69,35.43) v1(75.82,44.19) v1(76.05,68.71) v1(75.96,66.16) v1(76.45,23.37) v1(76.66,102.24) v1(76.71,98.42) v1(76.87,11.57) v1(76.87,7.76) v1(77.6,41.4) v1(77.6,36.45) v1(77.67,9.57) v1(78.99,19.05) v1(79.5,44.19) v1(79.76,36.45) v1(79.76,35.18) v1(79.88,81.41) v1(80.01,100.58) v1(80.01,23.37) v1(80.47,102.24) v1(80.47,9.57) v1(80.68,11.57) v1(80.68,7.76) v1(81.03,36.45) v1(81.03,35.18) v1(82.19,58.55) v1(82.17,19.05) v1(83.57,75.06) v1(83.68,73.16) v1(83.82,36.45) v1(83.82,35.18) v1(84.28,102.24) v1(84.33,44.96) v1(84.28,9.57) v1(84.49,11.57) v1(84.49,7.76) v1(85.09,36.45) v1(85.09,35.18) v1(85.67,56.72) v1(85.85,99.06) v1(85.85,94.99) v1(85.98,87.5) v1(85.98,86.36) v1(86.36,50.42) v1(86.87,100.07) v1(86.87,99.06) v1(86.87,73.28) v1(87,44.58) v1(87.25,25.27) v1(87.25,14.1) v1(87.63,36.45) v1(87.63,35.18) v1(87.76,50.42) v1(87.88,99.06) v1(88.09,102.24) v1(88.09,9.57) v1(88.3,11.57) v1(88.3,7.76) v1(88.9,36.45) v1(88.9,35.18) v1(89.15,96.52) v1(89.15,94.23) v1(89.65,67.41) v1(90.17,19.3) v1(90.81,100.07) v1(90.81,99.06) v1(91.06,25.27) v1(91.57,50.42) v1(91.69,86.36) v1(91.69,36.45) v1(91.69,35.18) v1(91.9,102.24) v1(91.9,98.43) v1(91.9,9.57) v1(92.11,11.57) v1(92.11,7.76) v1(92.71,86.36) v1(92.96,36.45) v1(92.96,35.18) v1(93.73,86.36) v1(94.11,74.93) v1(94.61,38.23) v1(94.61,35.18) v1(94.74,86.36) v1(94.74,43.81) v1(94.74,41.53) v1(94.87,14.1) v1(95.5,90.68) v1(95.71,102.24) v1(95.71,9.57) v1(95.76,86.36) v1(95.76,85.34) v1(95.92,11.57) v1(95.92,7.76) v1(97.41,90.68) v1(97.54,74.93) v1(97.66,42.16) v1(98.19,56.39) v1(98.42,38.23) v1(98.42,35.18) v1(99.19,99.06) v1(99.19,56.39) v1(99.19,55.12) v1(99.19,43.31) v1(99.19,42.16) v1(99.52,102.24) v1(99.52,9.57) v1(99.6,69.45) v1(99.73,11.57) v1(99.73,7.76) v1(99.9,24.66) v1(100.2,100.07) v1(100.2,99.06) v1(101.22,99.06) v1(101.45,28.09) v1(101.85,72.39) v1(102.23,80.63) v1(102.36,96.52) v1(102.58,20.19) v1(102.74,24.64) v1(102.74,23.24) v1(103.12,89.53) v1(103.33,102.24) v1(103.25,82.03) v1(103.54,7.76) v1(104.14,100.07) v1(104.14,99.06) v1(105.56,32.46) v1(105.56,31.44) v1(105.92,89.53) v1(105.92,44.07) v1(105.92,40.51) v1(105.92,38.48) v1(105.92,37.46) v1(105.92,36.45) v1(105.92,35.43) v1(105.92,34.42) v1(105.92,33.4) v1(106.68,75.18) v1(106.71,33.68) v1(106.93,39.5) v1(106.93,38.48) v1(106.93,36.45) v1(106.93,35.43) v1(107.01,41.07) v1(107.04,40.26) v1(107.14,102.24) v1(107.35,11.57) v1(107.35,7.76) v1(107.7,93.85) v1(107.7,23.24) v1(107.85,40.74) v1(107.95,42.54) v1(107.95,41.58) v1(108.05,31.47) v1(108.53,82.17) v1(108.58,100.07) v1(108.58,97.66) v1(108.58,94.99) v1(108.58,92.84) v1(108.58,88.64) v1(108.58,86.1) v1(108.58,83.95) v1(108.84,42.85) v1(108.81,41.73) v1(108.84,29.08) v1(109.17,43.64) v1(109.24,23.28) v1(109.3,38.1) v1(109.4,36.93) v1(109.42,35.94) v1(109.37,34.9) v1(109.37,33.78) v1(109.7,42.48) v1(109.98,83.16) v1(109.98,44.07) v1(109.96,39.37) v1(109.98,38.48) v1(109.98,37.46) v1(109.98,34.42) v1(109.98,33.4) v1(110.13,43.31) v1(110.09,36.41) v1(110.09,35.39) v1(110.36,68.32) v1(110.36,67.05) v1(110.95,102.24) v1(111,43.56) v1(111,39.5) v1(111,38.48) v1(111,37.46) v1(111,36.45) v1(111,35.43) v1(111,34.42) v1(111,33.4) v1(111,32.38) v1(111,31.37) v1(111.1,40.44) v1(111.16,11.57) v1(111.16,7.76) v1(111.28,83.16) v1(111.63,69.59) v1(111.63,68.32) v1(111.63,67.05) v1(111.89,44.07) v1(112.01,40.51) v1(112.01,39.5) v1(112.01,38.48) v1(112.01,37.46) v1(112.57,41.71) v1(112.9,69.59) v1(112.9,68.32) v1(112.9,67.05) v1(112.9,44.07) v1(113.03,39.5) v1(113.03,38.48) v1(113.67,61.34) v1(113.79,32.33) v1(114.05,39.5) v1(114.05,38.48) v1(114.76,102.24) v1(114.81,18.16) v1(114.88,38.96) v1(114.97,7.76) v1(115.44,75.18) v1(115.75,83.39) v1(115.82,41.53) v1(115.82,40.51) v1(115.82,39.5) v1(115.82,38.48) v1(116.46,100.71) v1(117.35,66.04) v1(117.47,100.71) v1(117.47,23.24) v1(117.47,16.25) v1(117.98,36.32) v1(118.57,102.24) v1(118.75,23.24) v1(118.78,7.76) v1(119.13,66.04) v1(119.25,97.79) v1(119.96,45.67) v1(120.27,52.96) v1(120.78,68.32) v1(120.78,38.48) v1(120.78,36.45) v1(121.79,54.23) v1(122.05,23.24) v1(122.3,51.81) v1(122.38,102.24) v1(122.59,11.57) v1(122.59,7.76) v1(122.81,16.38) v1(123.06,66.04) v1(123.11,55.12) v1(123.19,30.73) v1(123.19,29.21) v1(123.44,40.51) v1(123.57,52.7) v1(123.7,25.27) v1(124.13,66.07) v1(124.08,33.91) v1(124.4,55.02) v1(124.59,42.54) v1(124.59,41.53) v1(124.59,40.51) v1(124.71,30.73) v1(124.71,29.21) v1(125.09,36.32) v1(125.09,33.91) v1(125.22,22.73) v1(125.48,100.07) v1(125.48,97.53) v1(125.6,42.54) v1(125.6,41.53) v1(125.6,40.51) v1(125.73,62.48) v1(126.19,102.24) v1(126.4,7.76) v1(126.49,18.03) v1(127.63,62.48) v1(127.64,57.91) v1(127.64,48.13) v1(127.64,36.32) v1(128.43,18.62) v1(129.03,84.71) v1(129.29,93.6) v1(129.29,38.99) v1(129.29,36.7) v1(130,102.24) v1(130.05,84.71) v1(130.18,88.28) v1(130.21,7.77) v1(130.3,93.6) v1(130.3,38.99) v1(130.68,91.57) v1(130.94,21.59) v1(130.94,20.57) v1(132.24,41.48) v1(132.24,37.67) v1(132.24,33.86) v1(132.24,30.05) v1(132.24,26.24) v1(132.24,22.43) v1(132.24,18.62) v1(132.24,14.81) v1(132.24,11)
